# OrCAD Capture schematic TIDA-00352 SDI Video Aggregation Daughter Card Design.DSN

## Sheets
1 S01 COVER PAGE
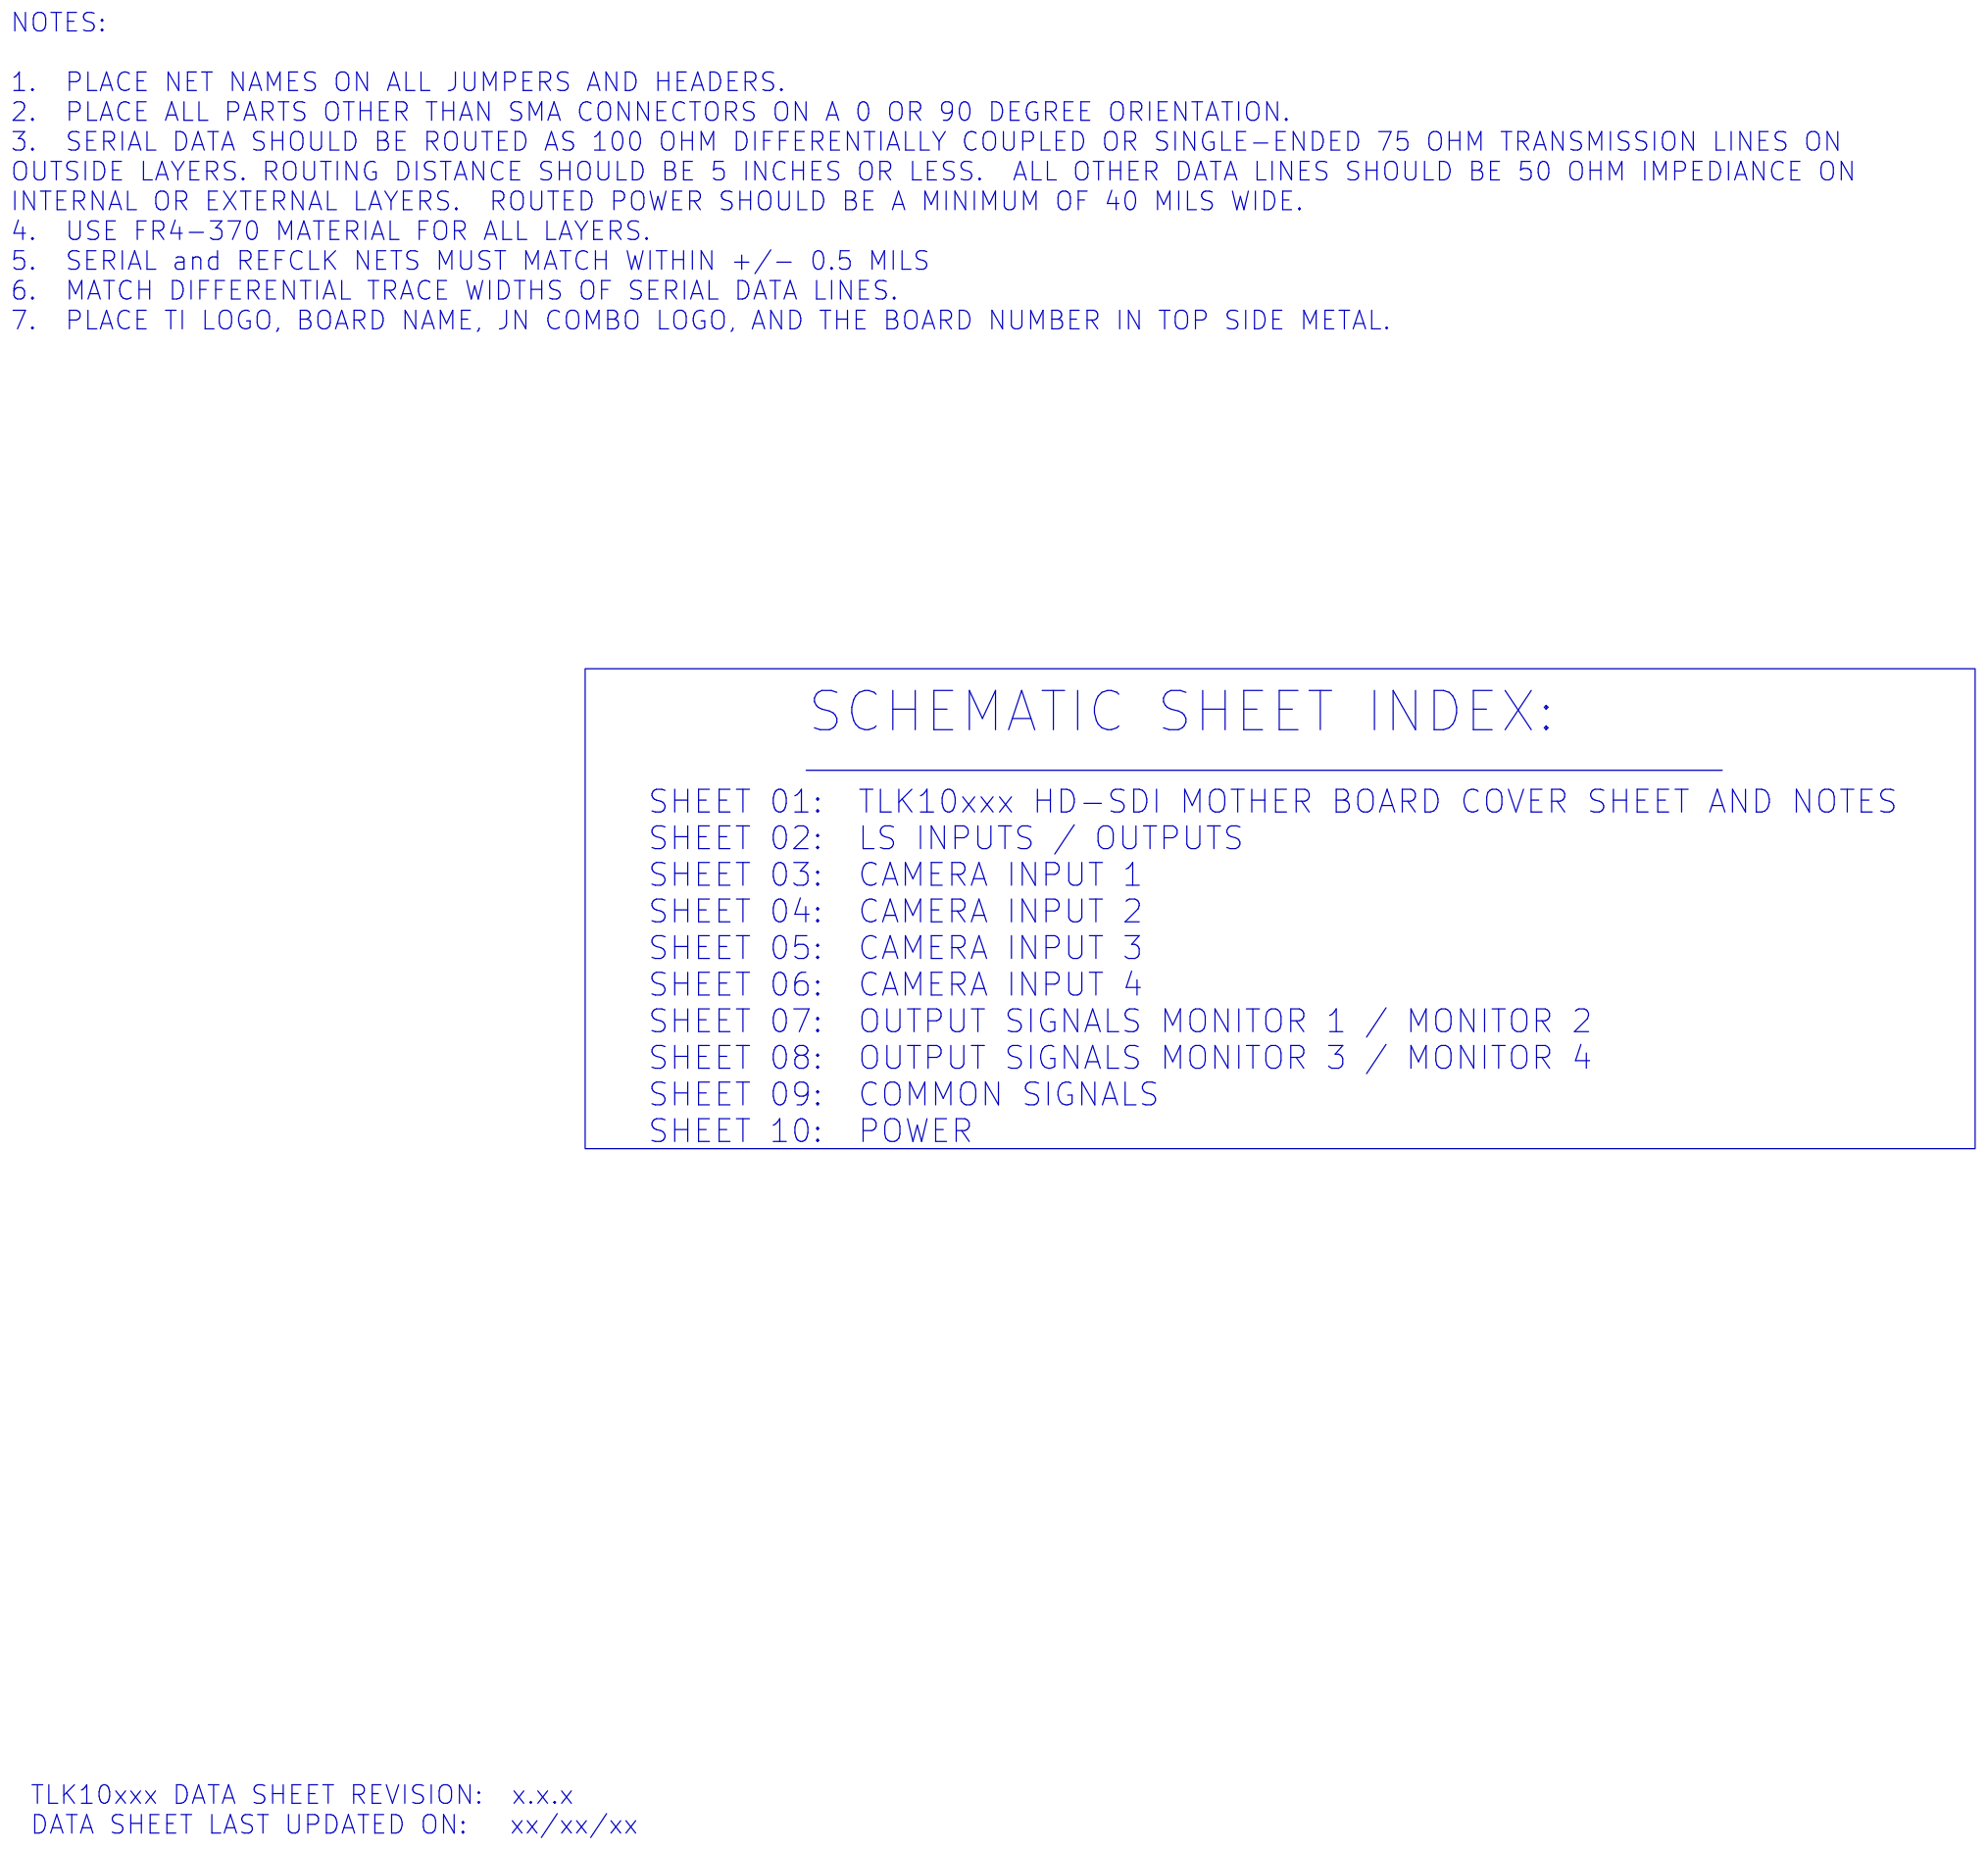
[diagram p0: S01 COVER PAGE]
2 S02 LS INPUTS_OUTPUTS: size B
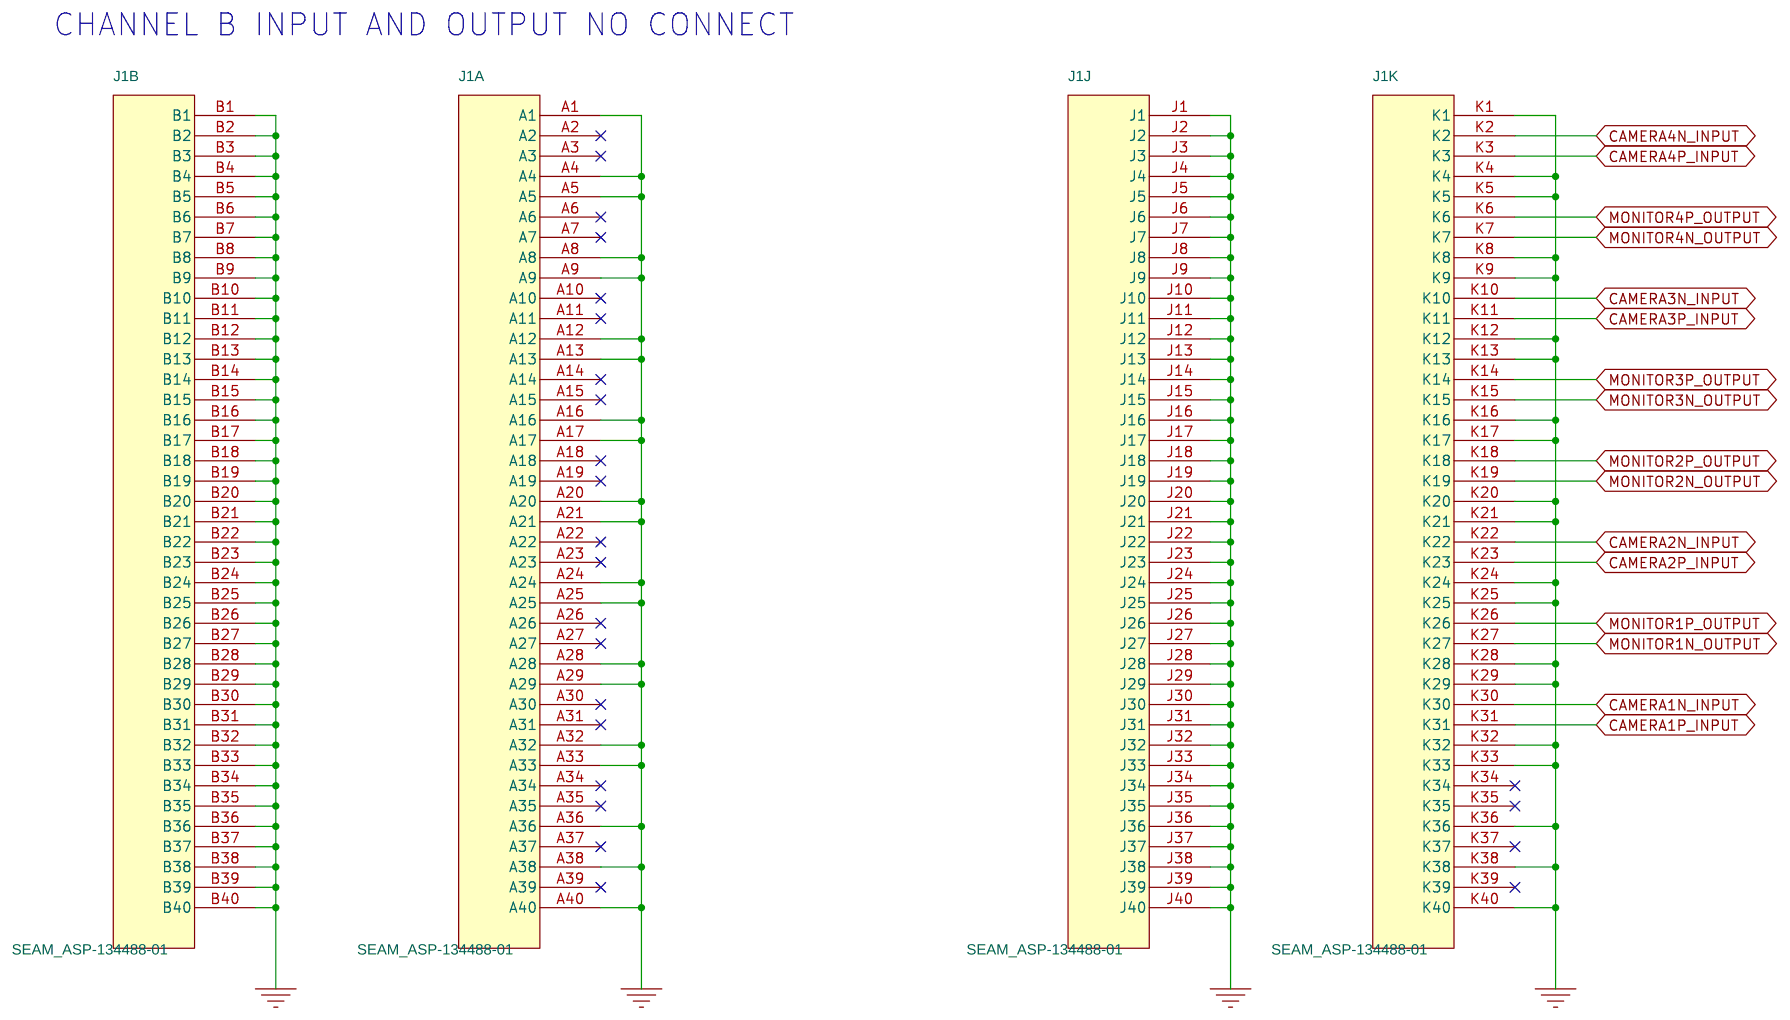
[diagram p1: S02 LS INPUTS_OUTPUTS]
3 S03 CAMERA INPUT 1: size B
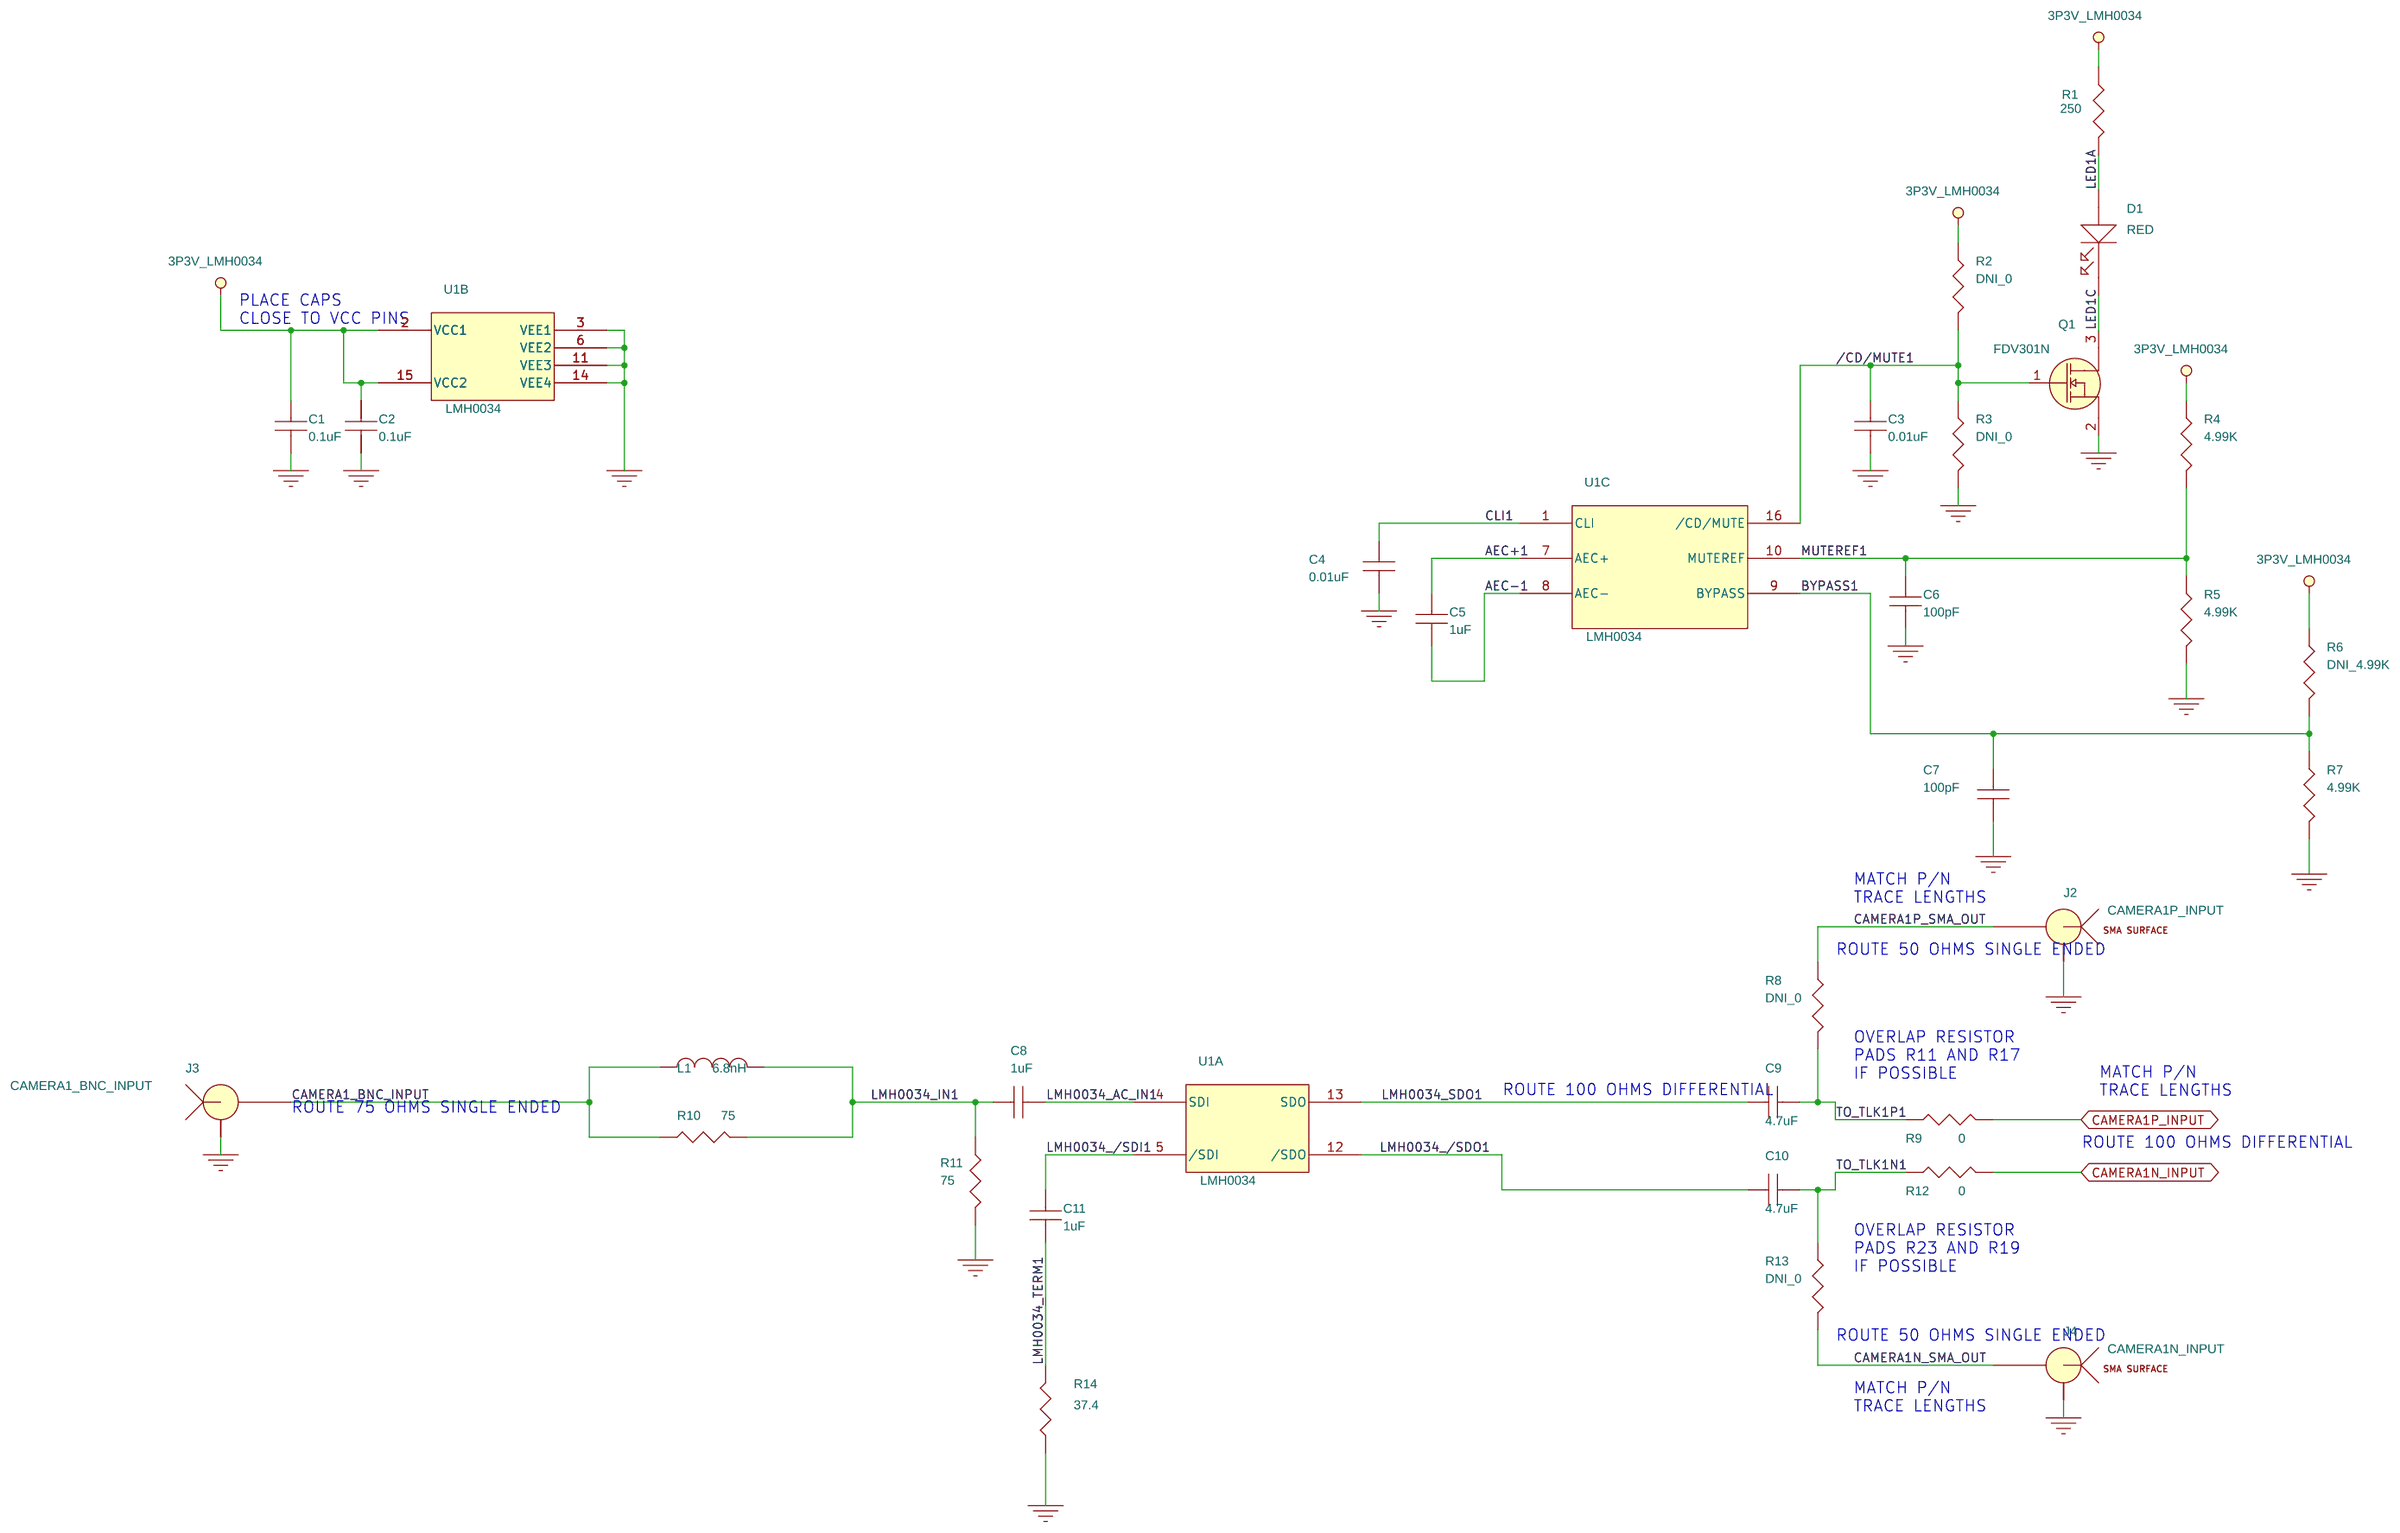
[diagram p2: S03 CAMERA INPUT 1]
4 S04 CAMERA INPUT 2: size B
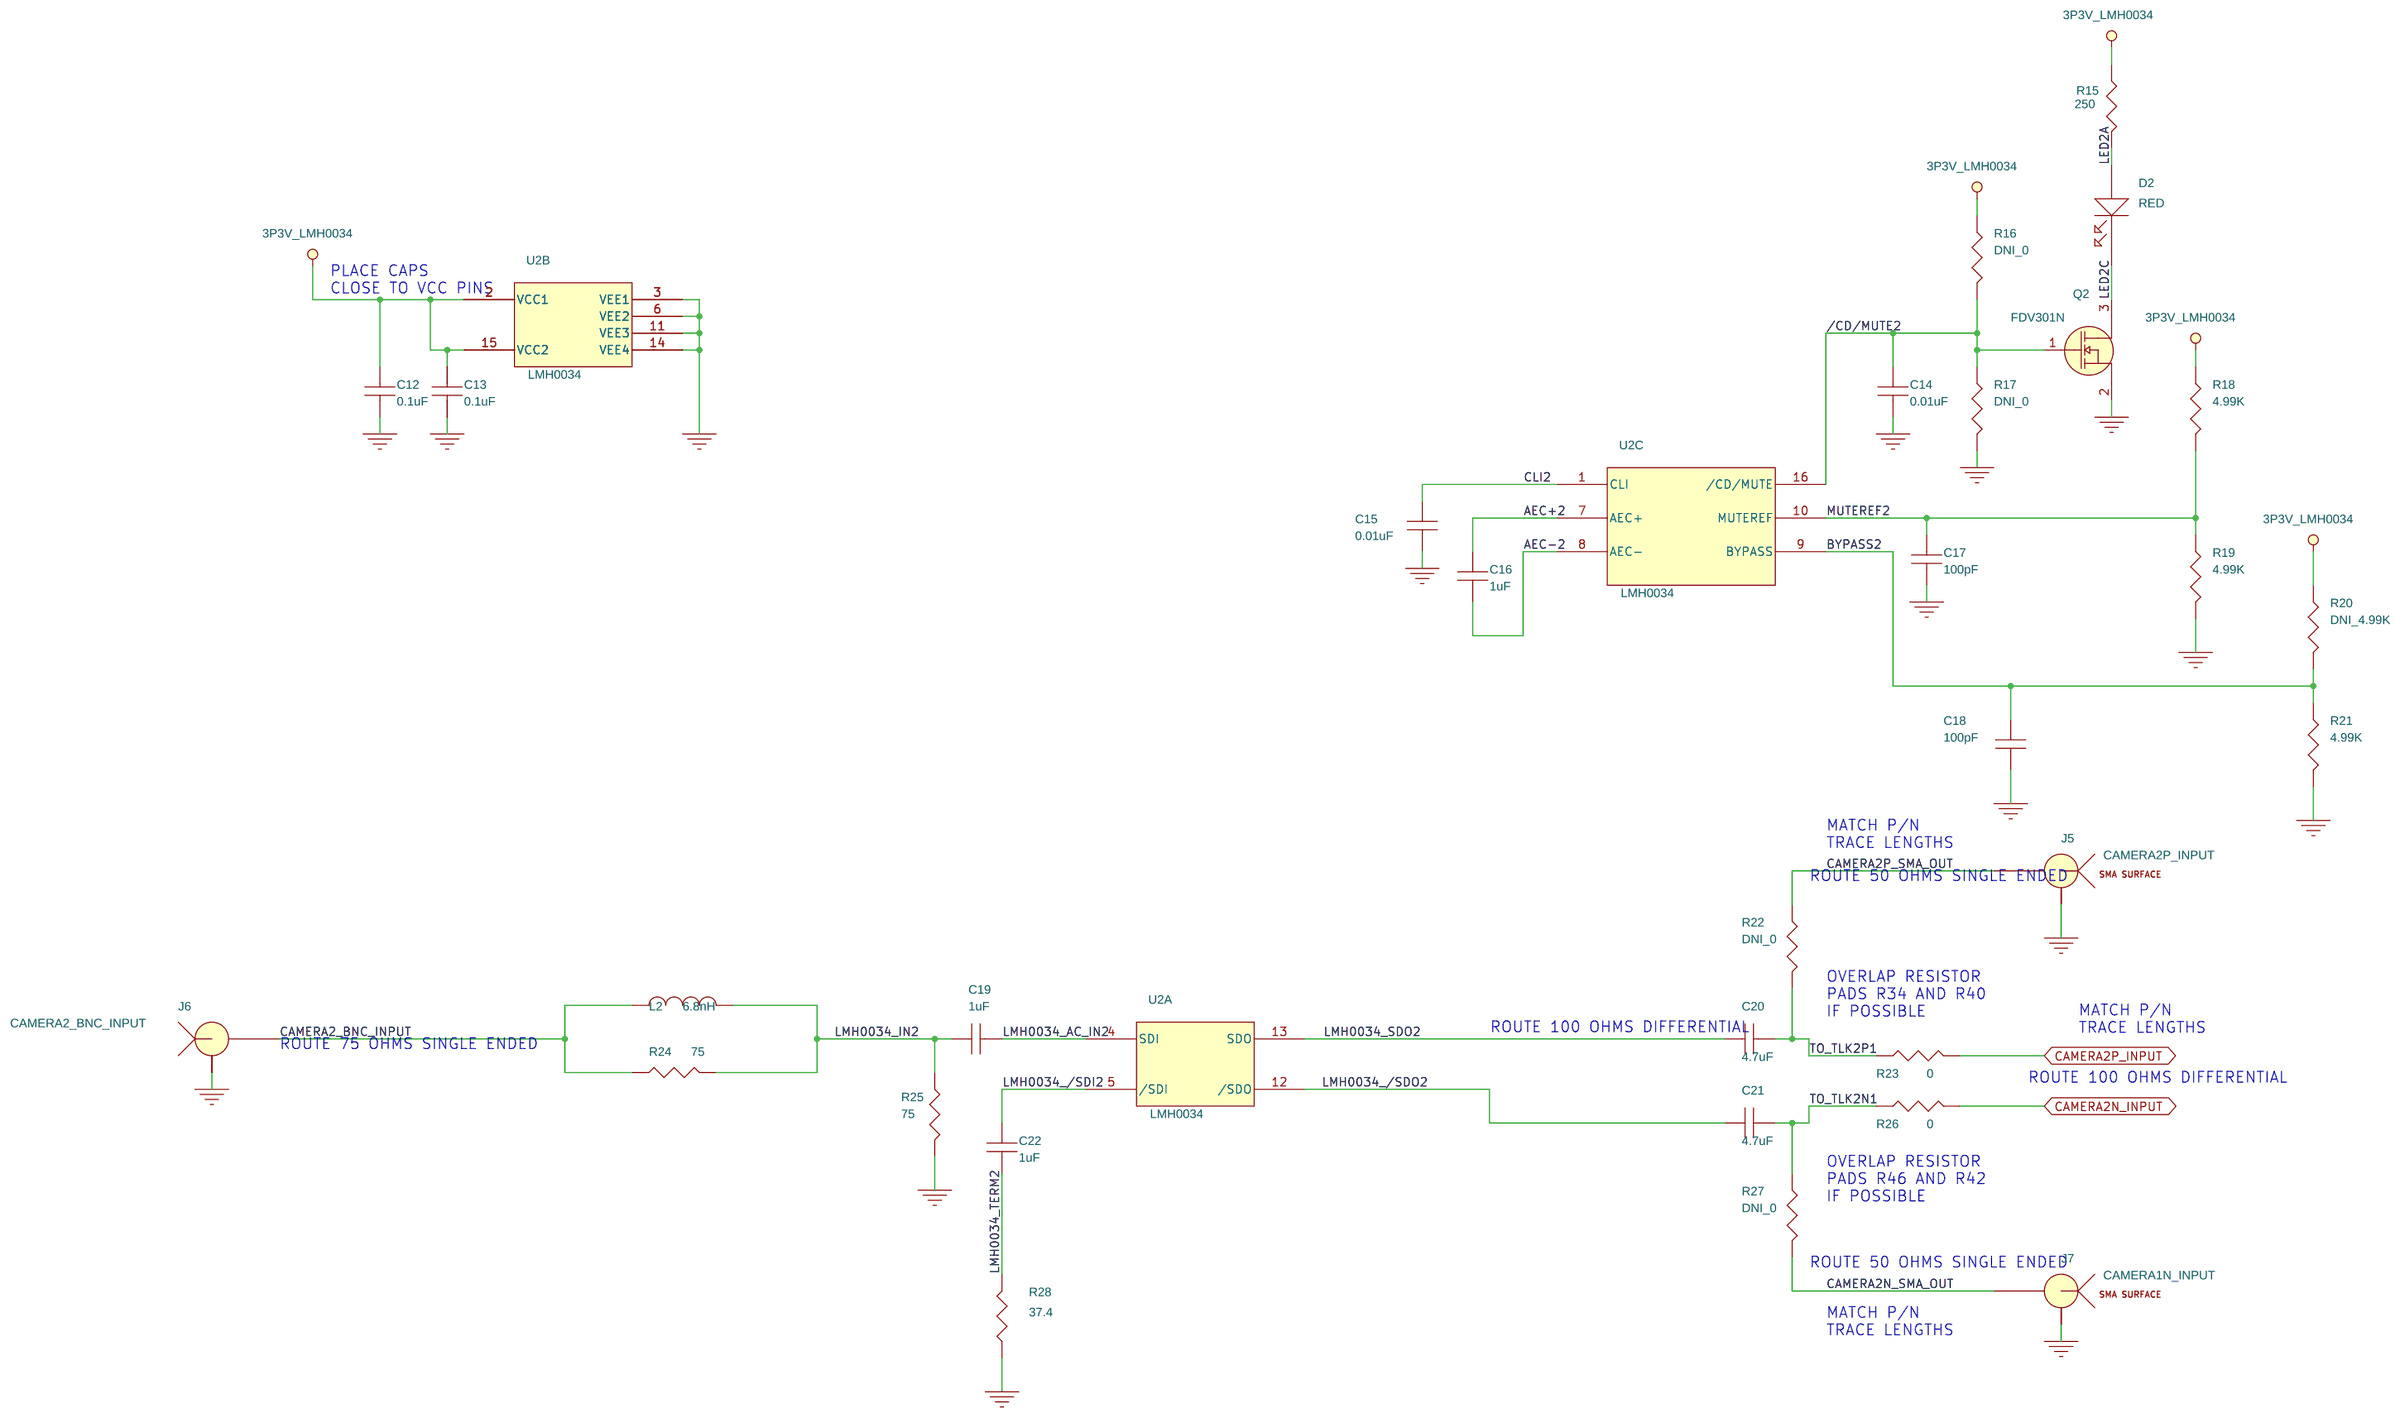
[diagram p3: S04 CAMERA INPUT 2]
5 S05 CAMERA INPUT 3: size B
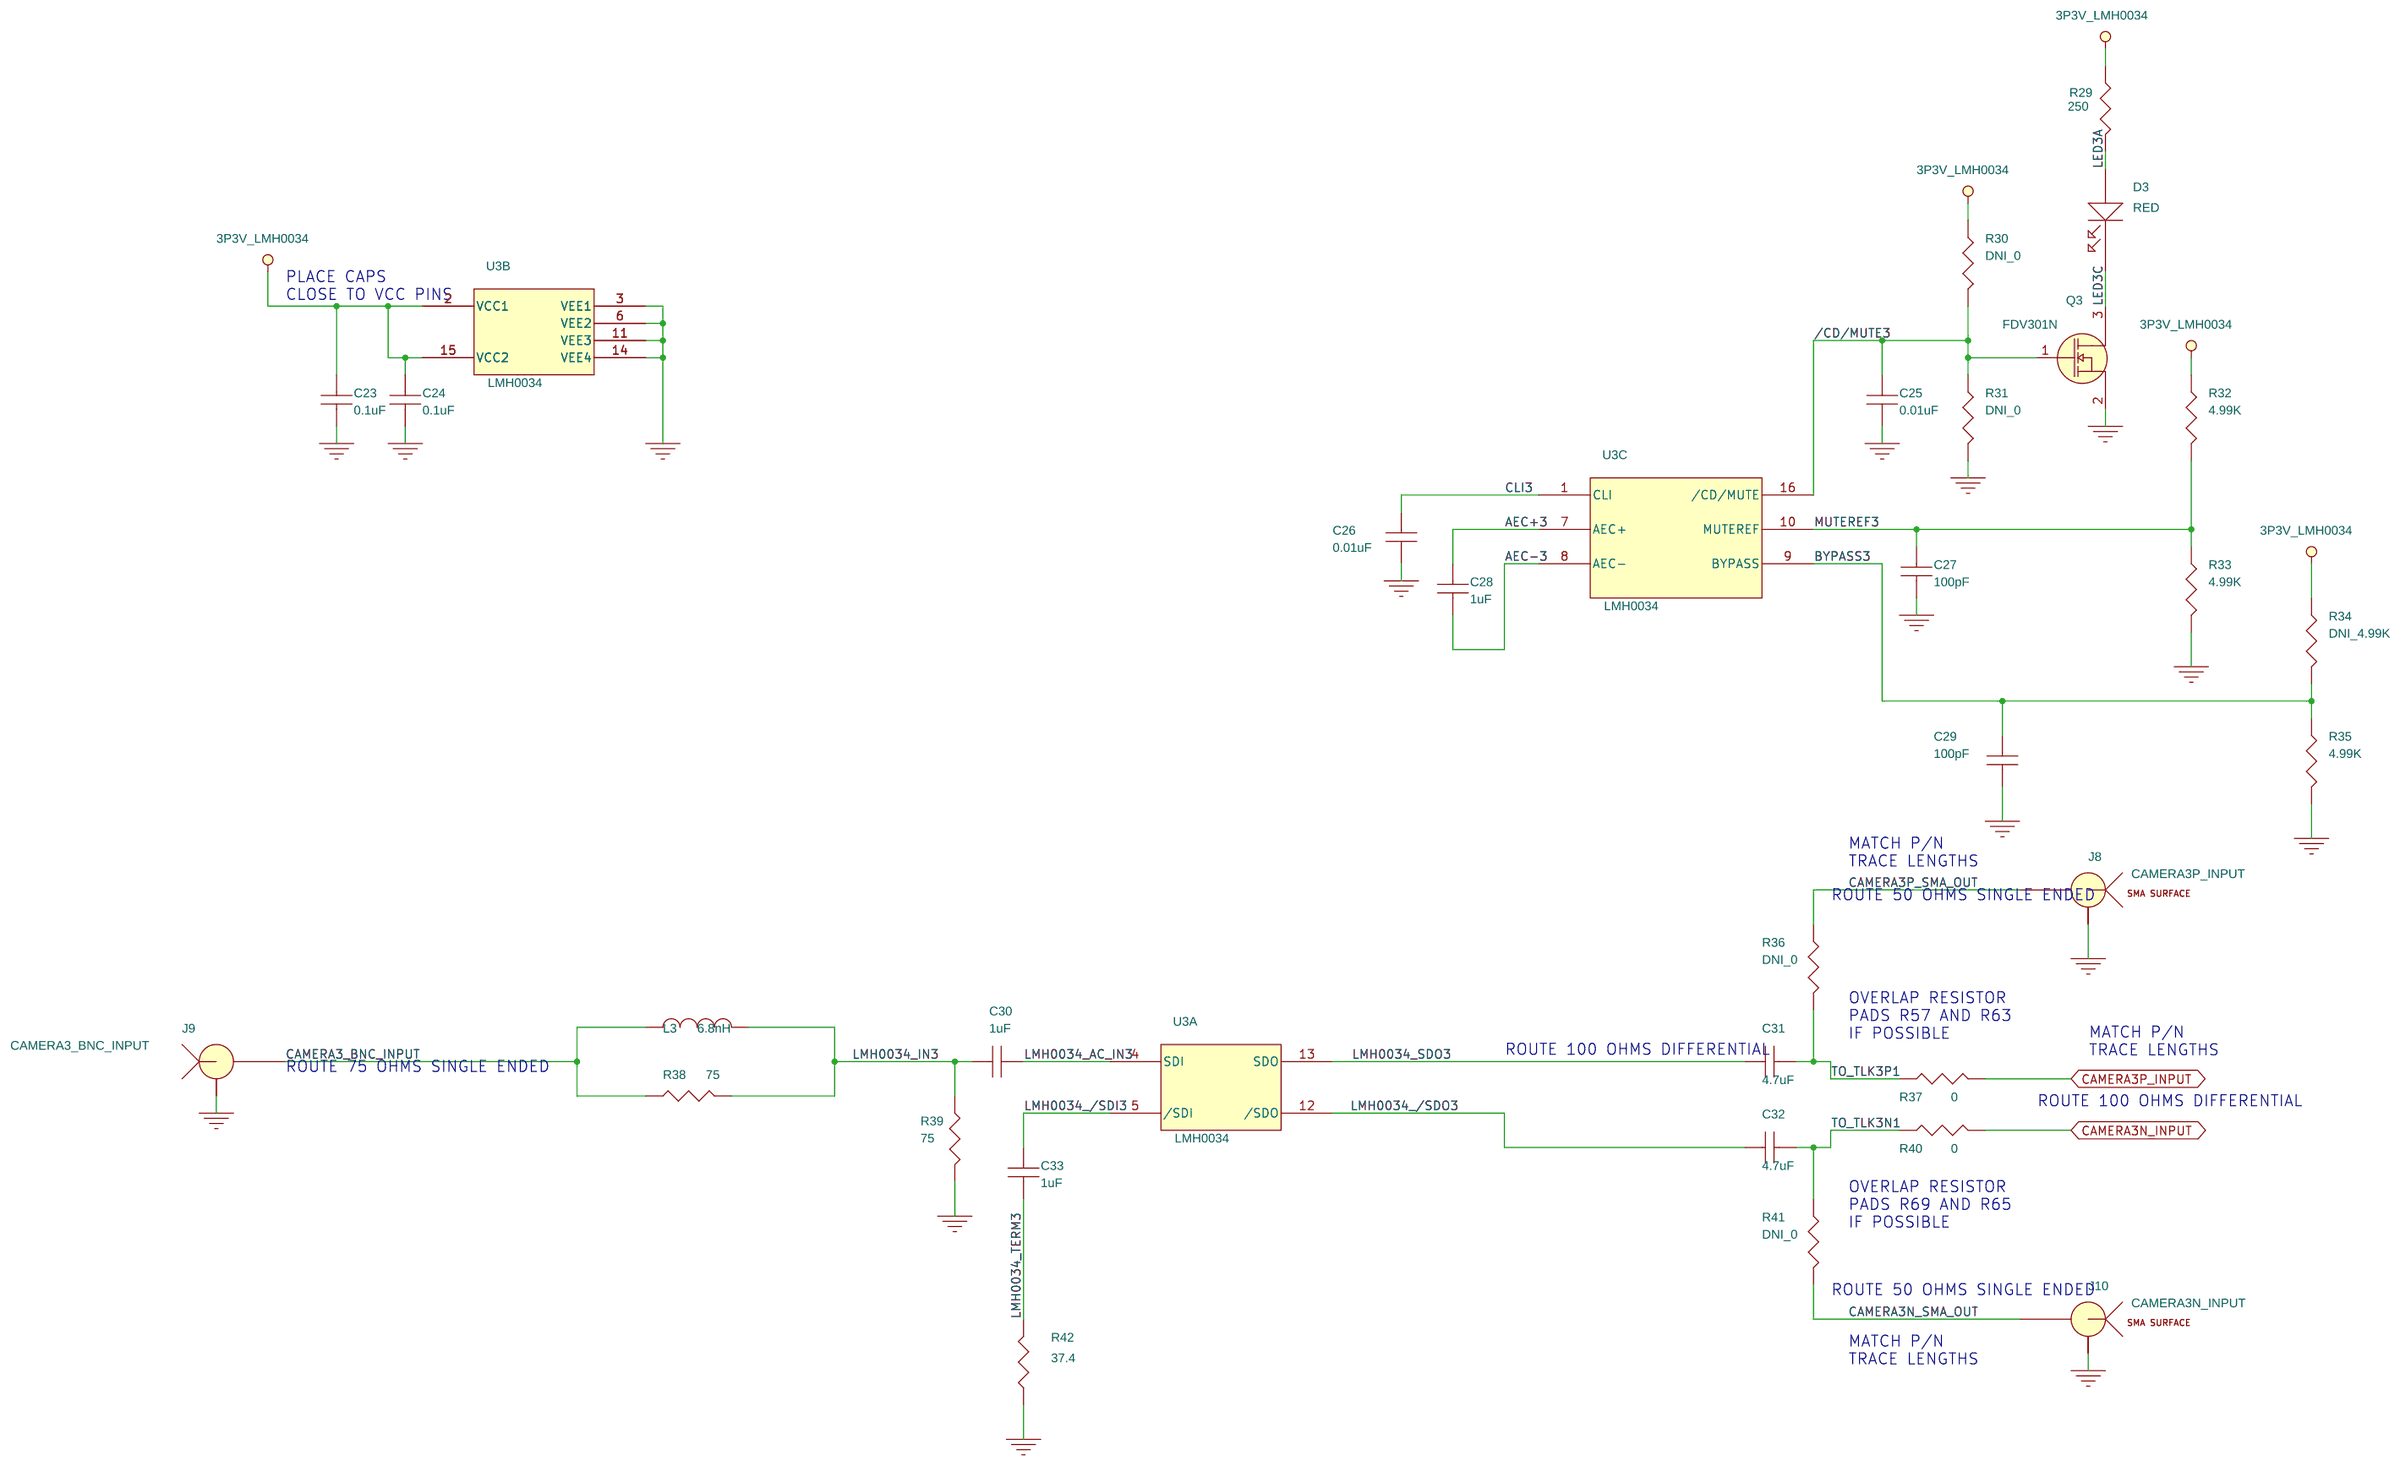
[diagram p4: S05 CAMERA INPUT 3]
6 S06 CAMERA INPUT 4: size B
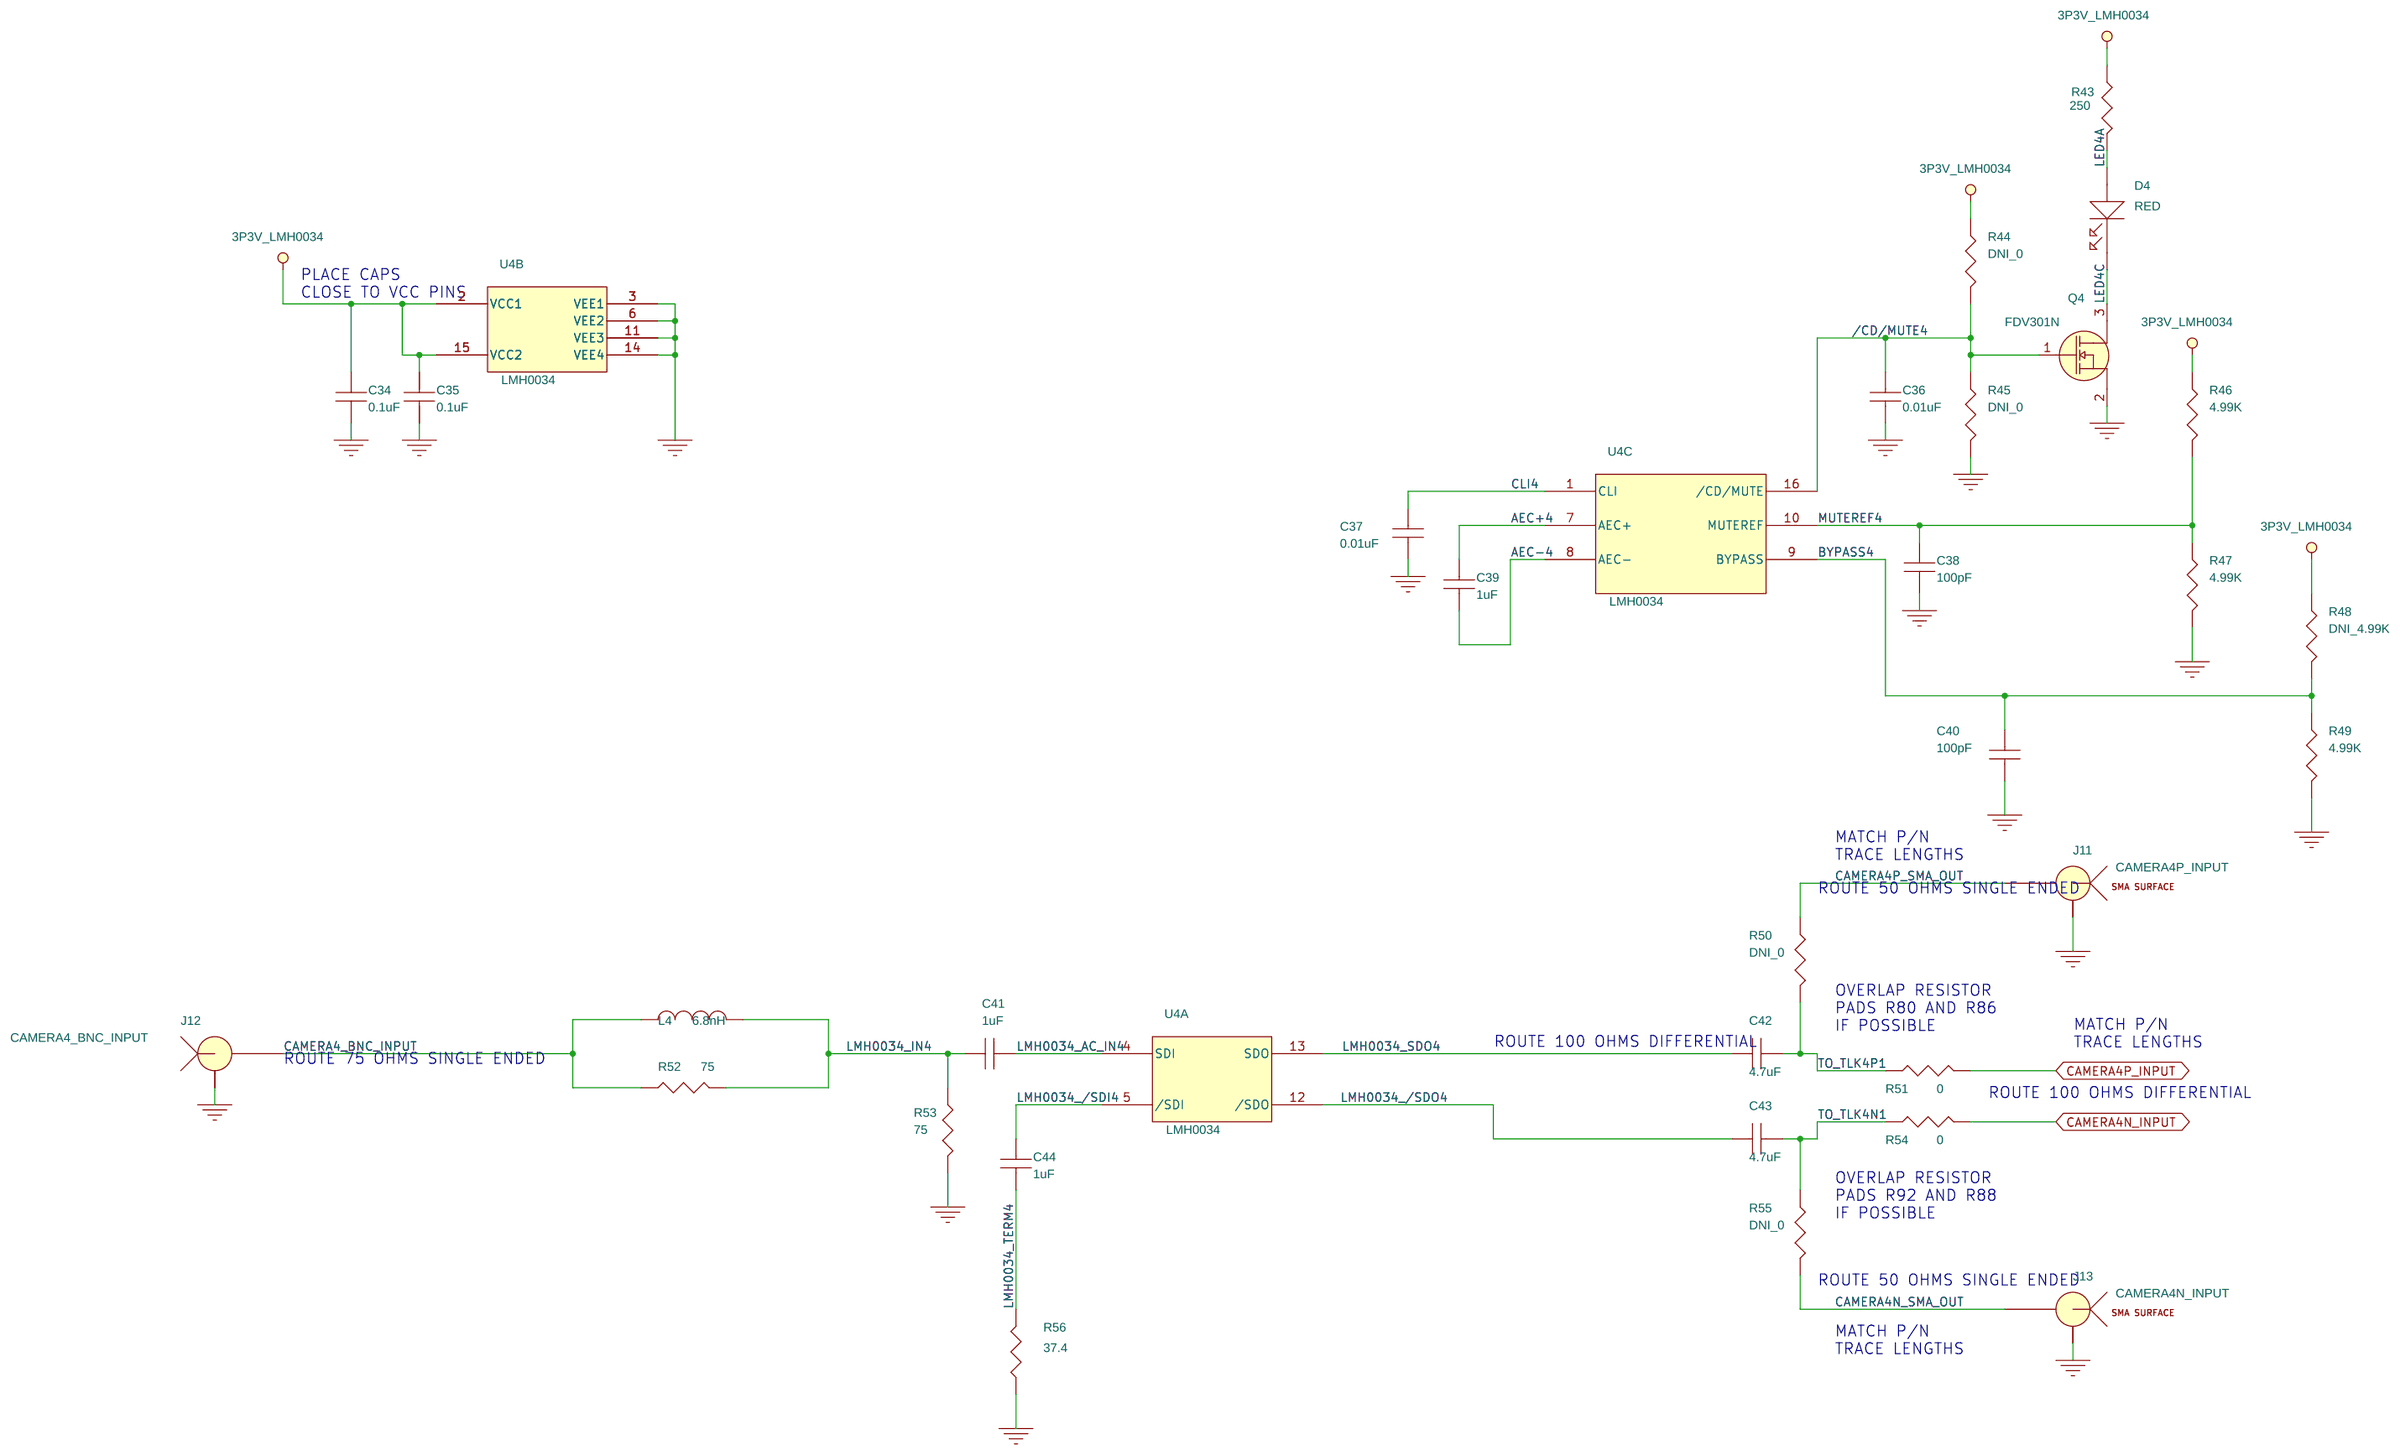
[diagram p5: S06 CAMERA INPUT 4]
7 S07 OUTPUT SIGNALS 1: size B
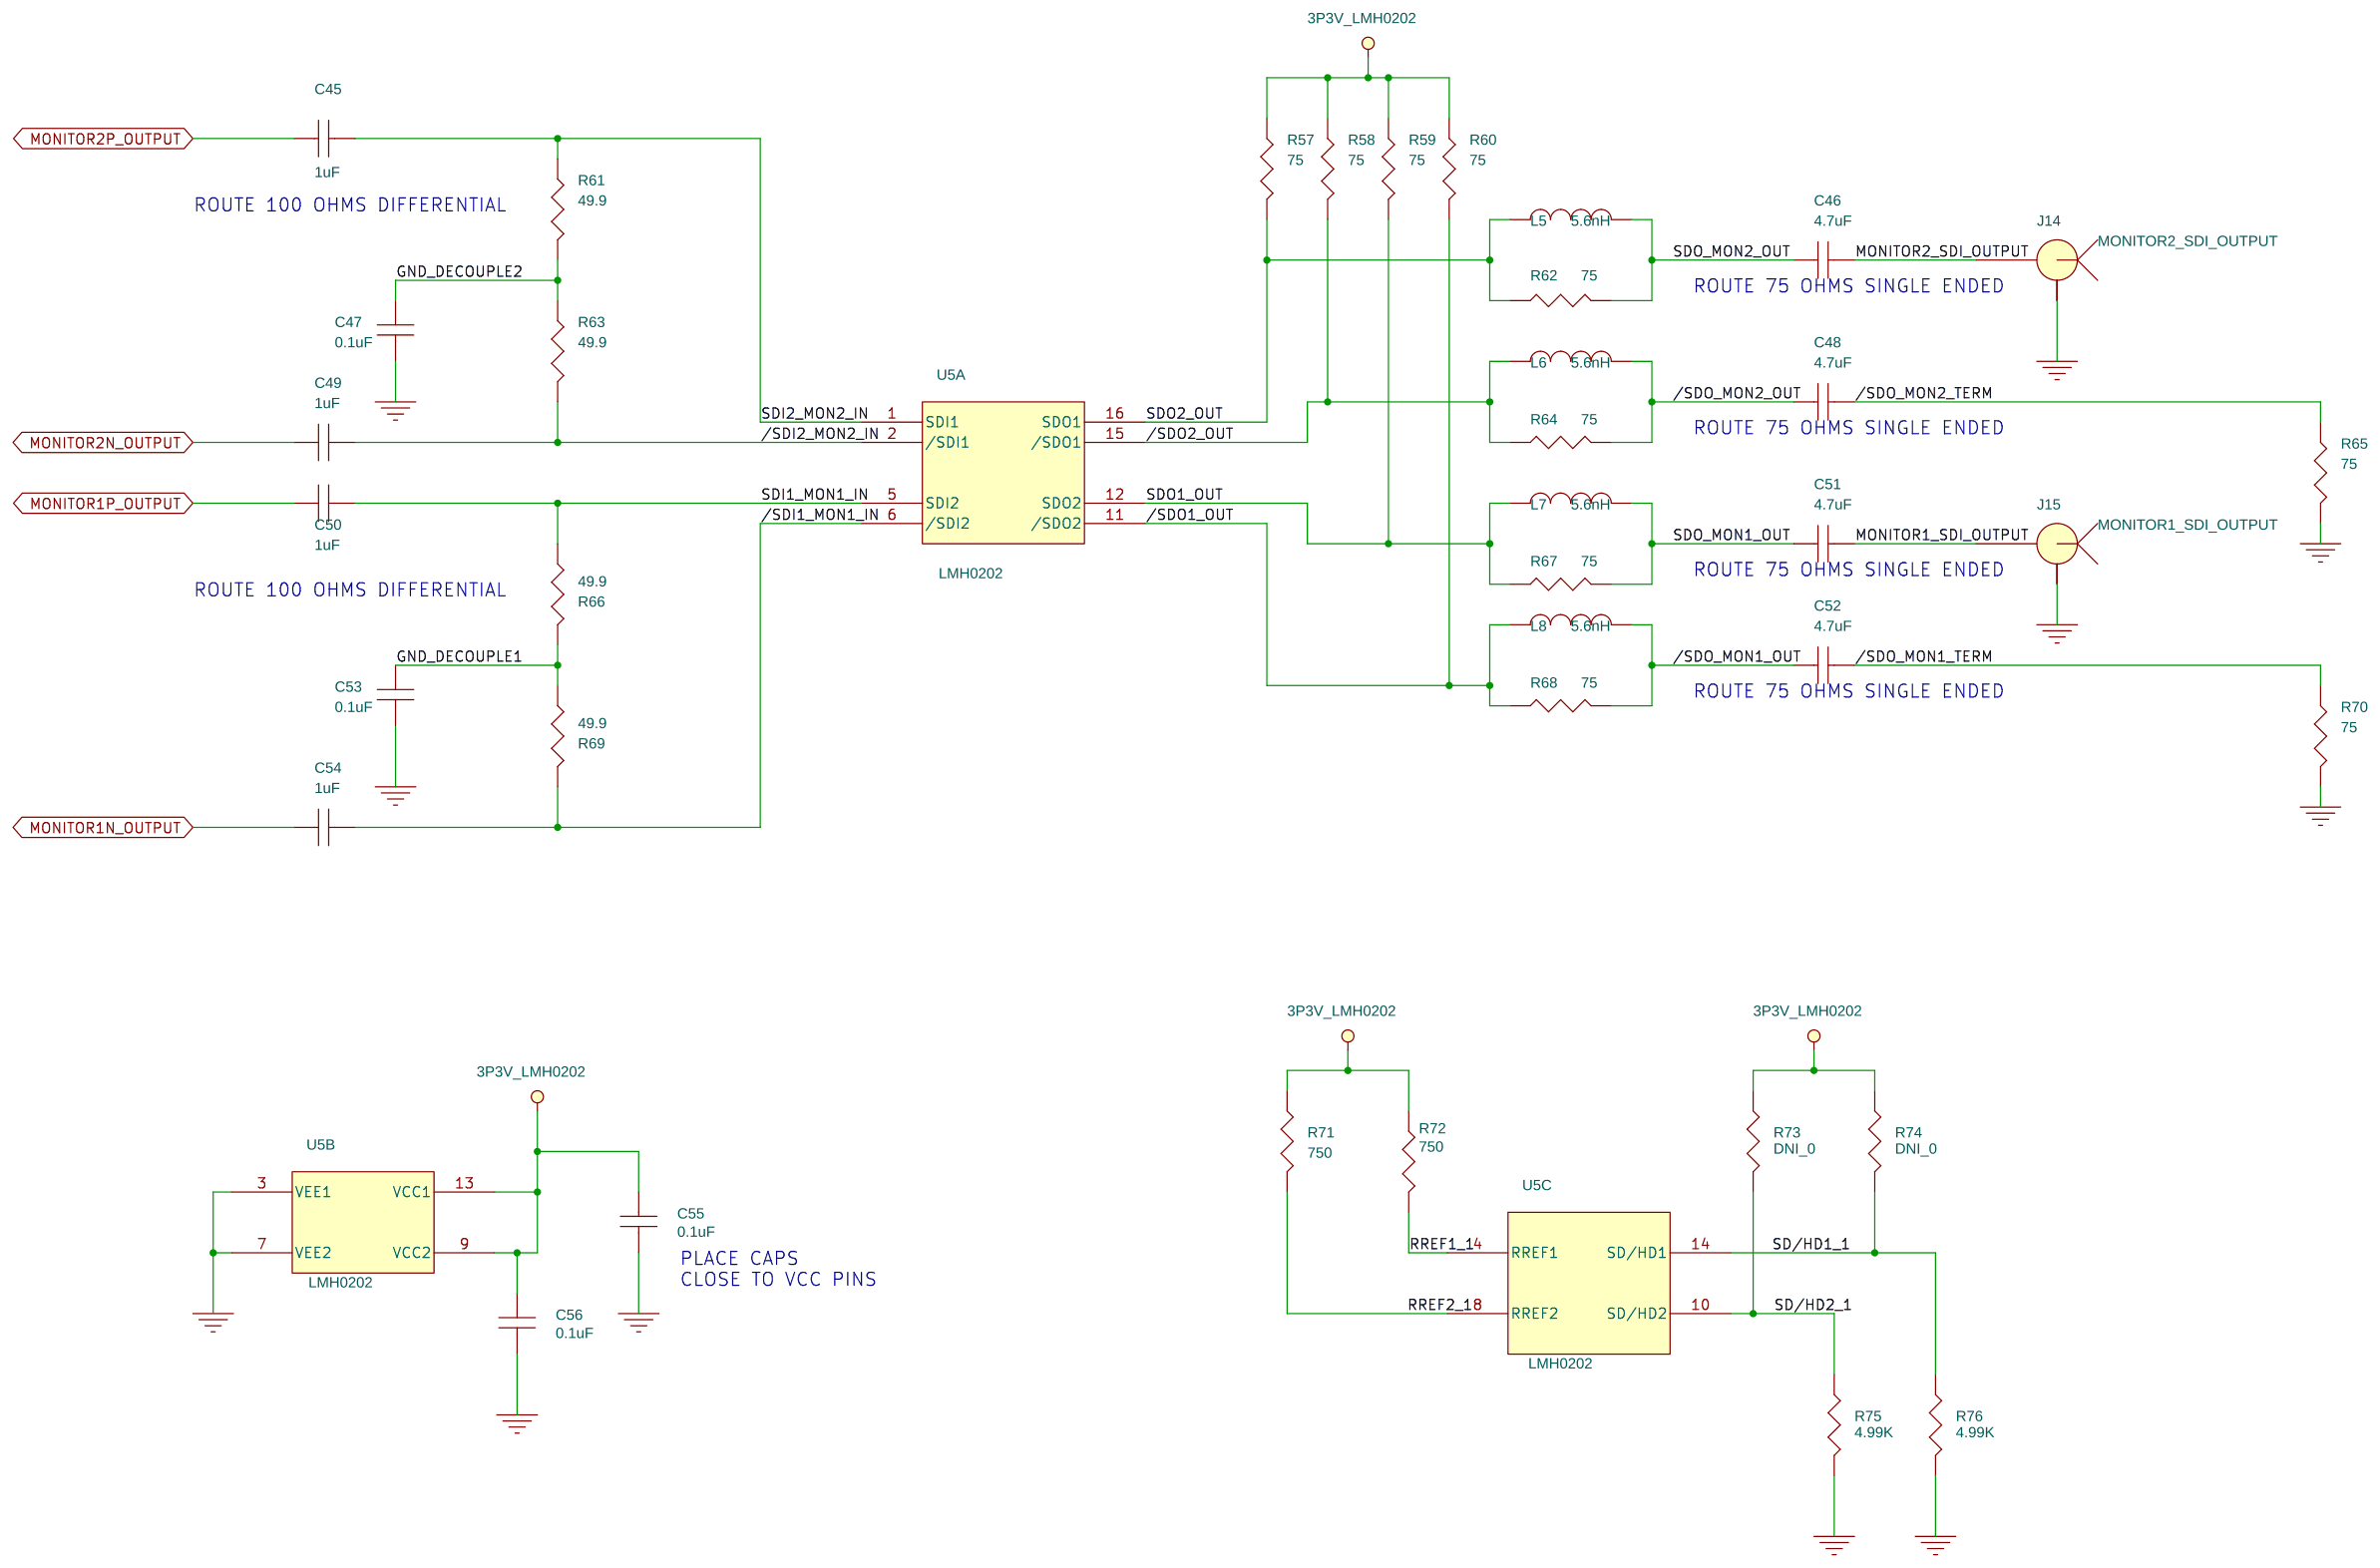
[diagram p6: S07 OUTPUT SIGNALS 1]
8 S08 OUTPUT SIGNALS 2: size B
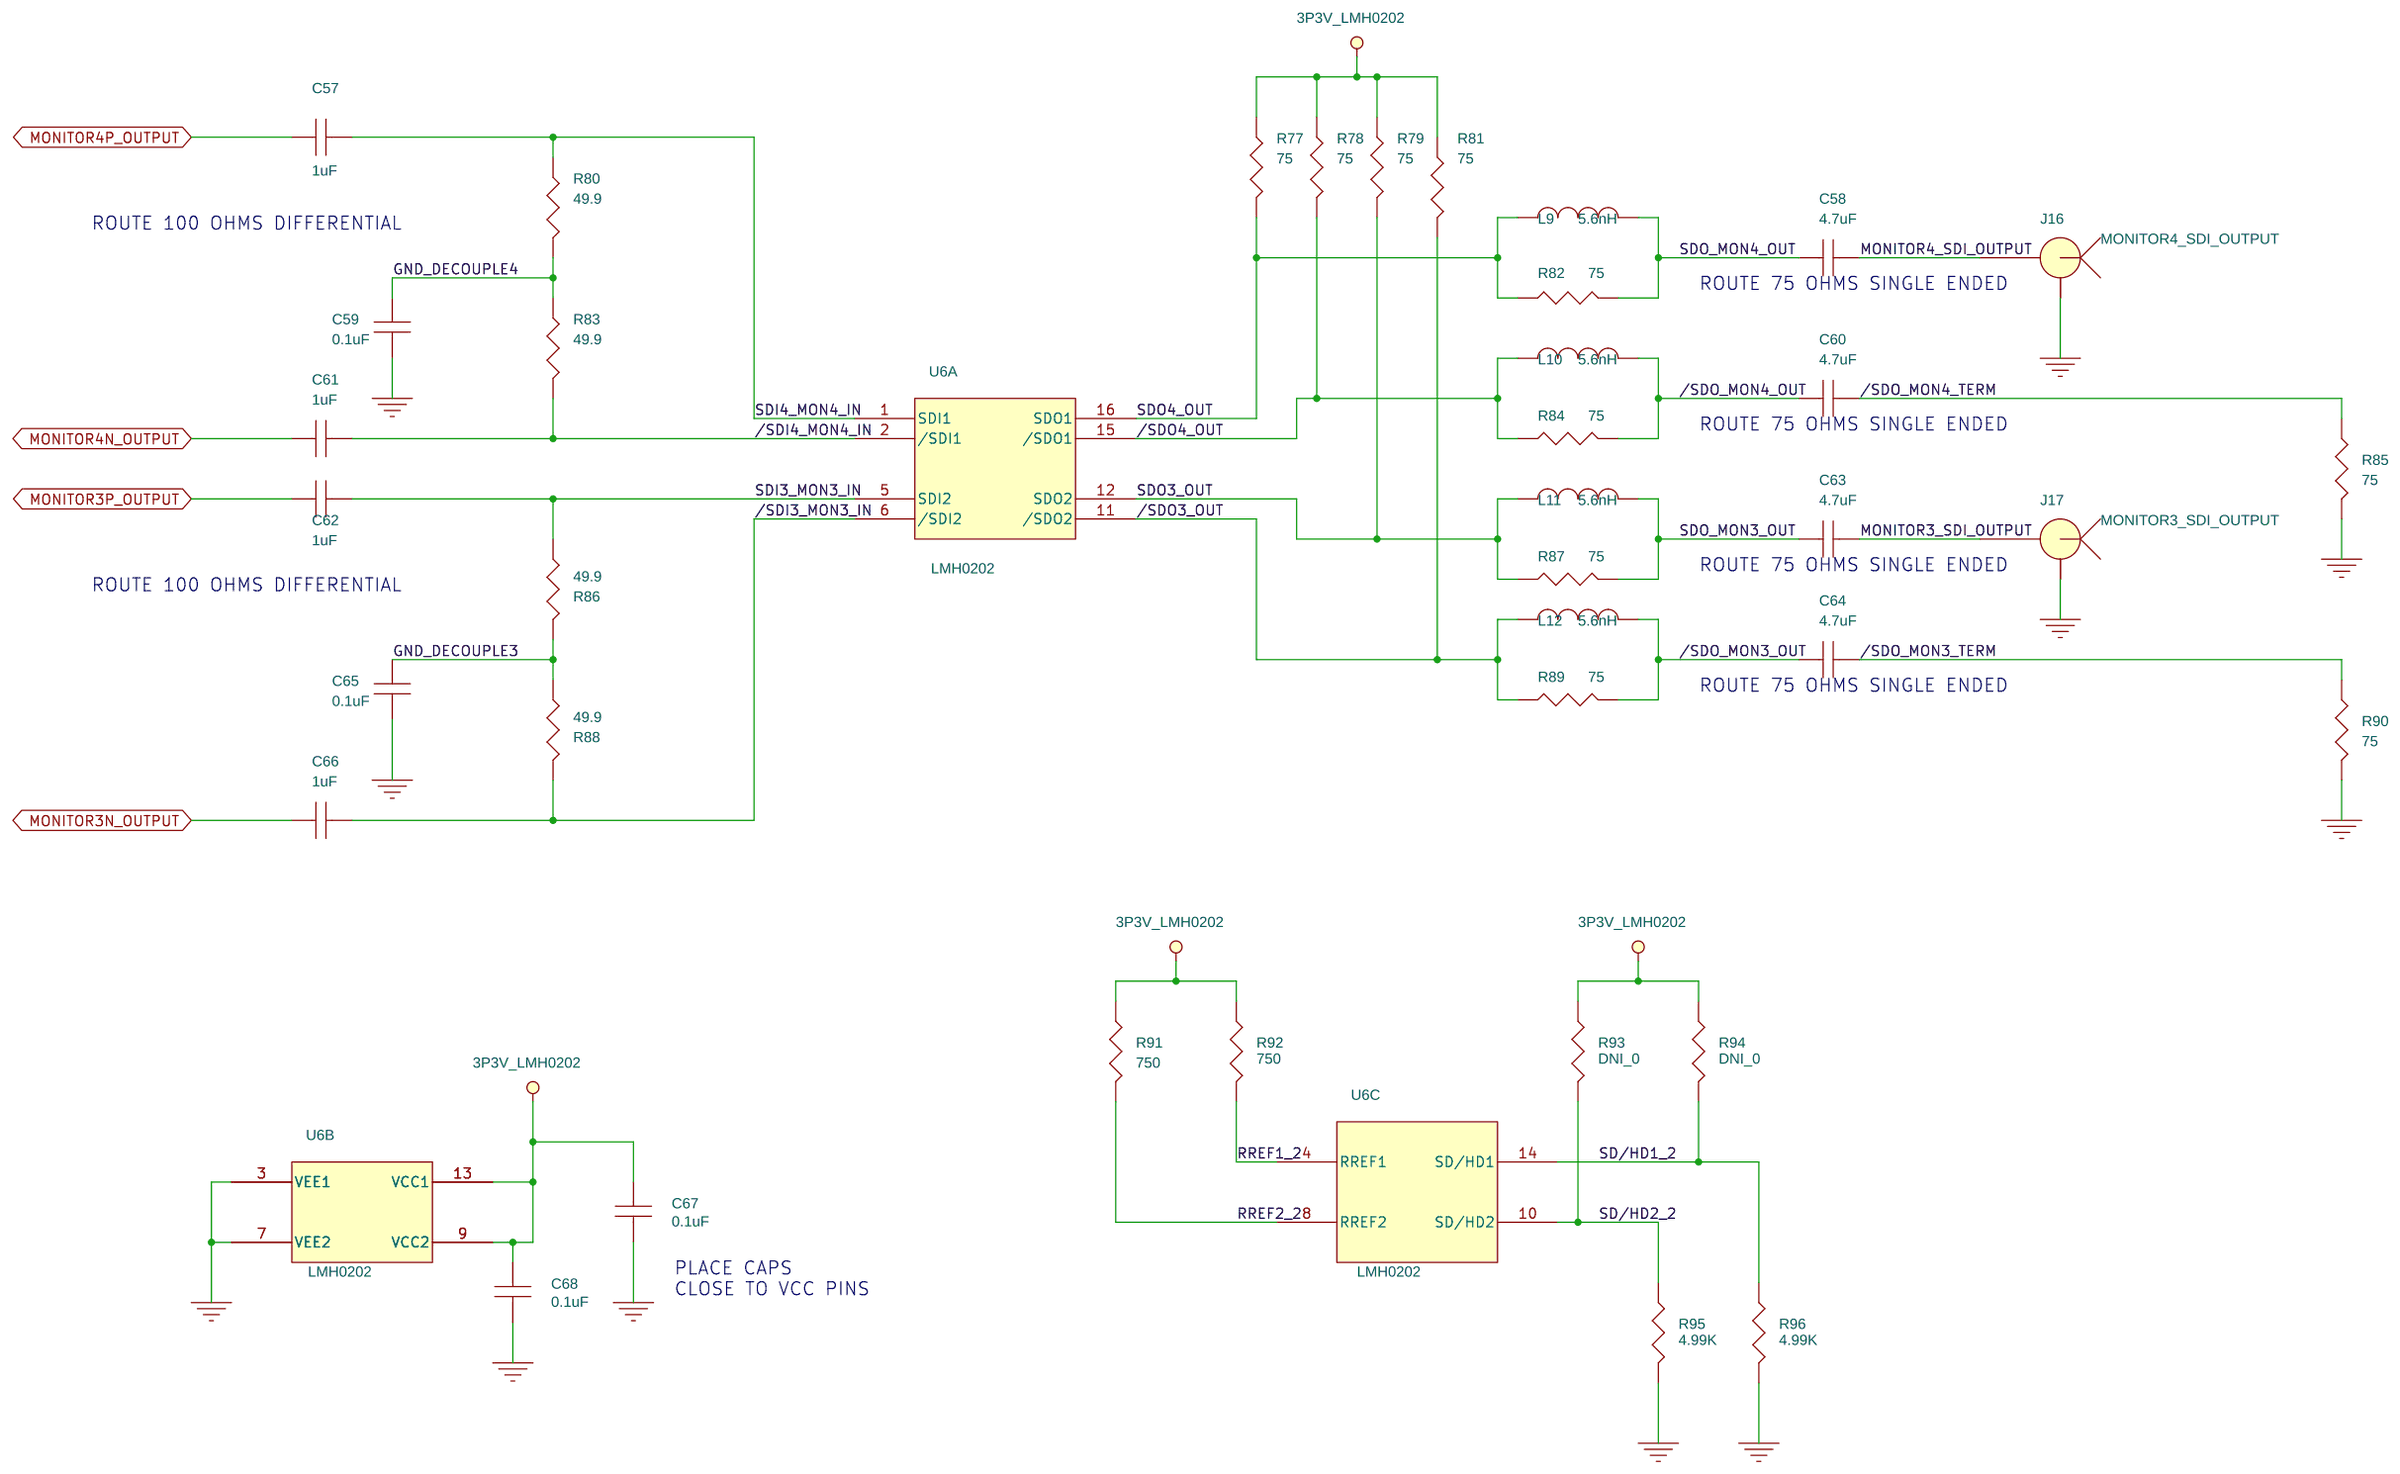
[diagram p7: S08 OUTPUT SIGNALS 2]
9 S09COMMON SIGNALS: size B
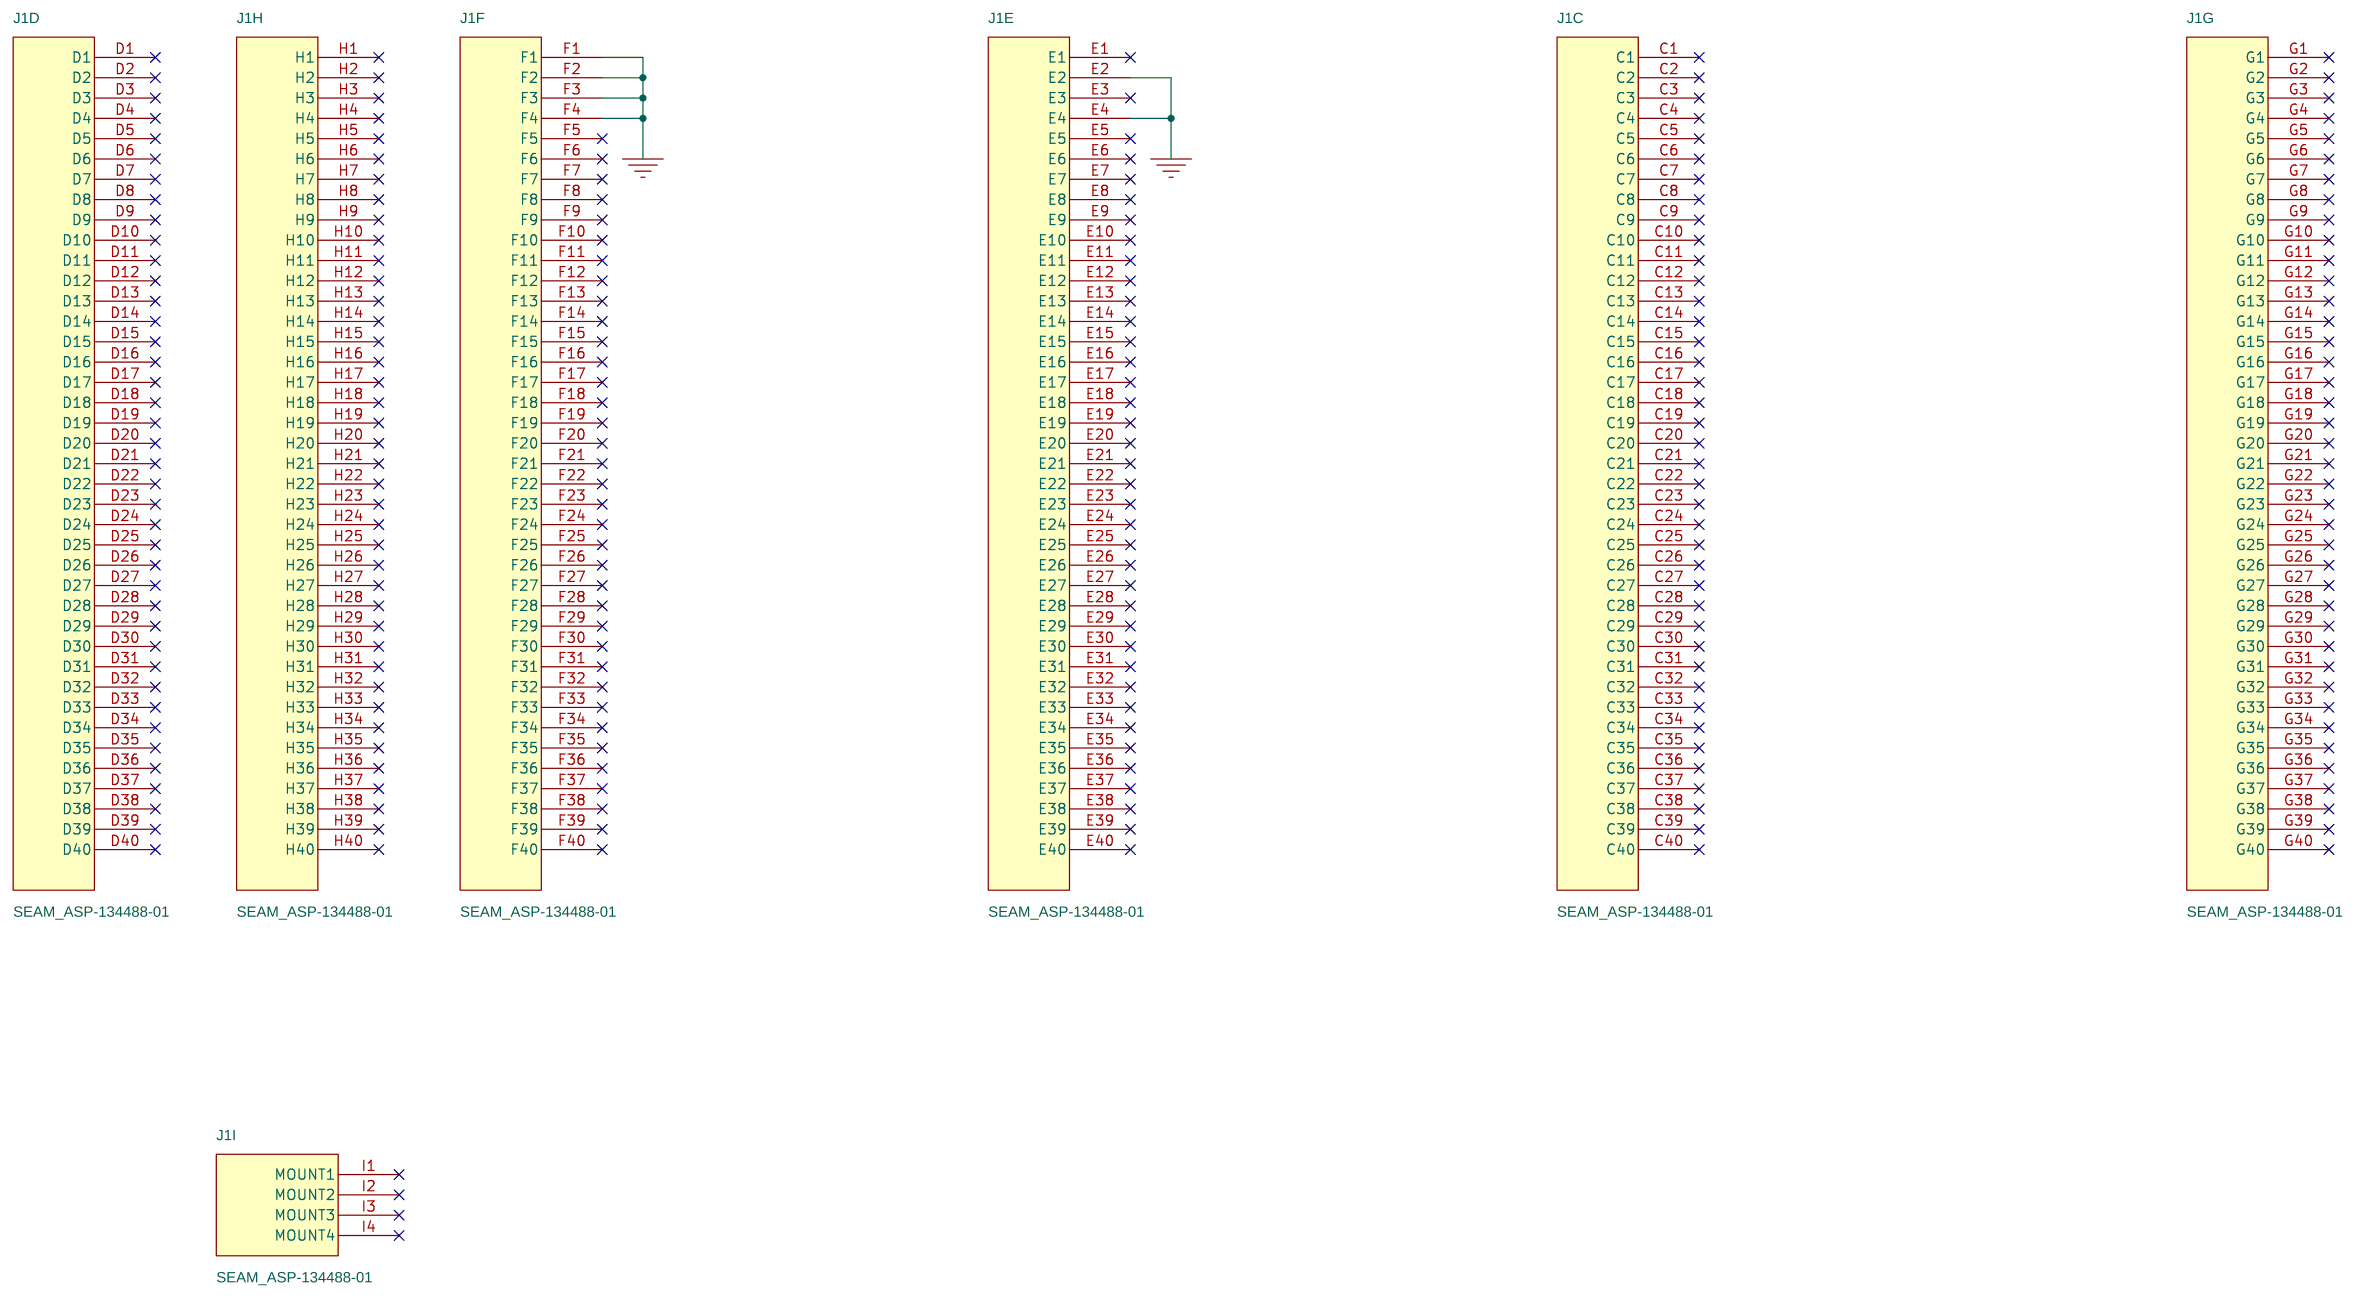
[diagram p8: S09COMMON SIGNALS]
10 S10 POWER: size B
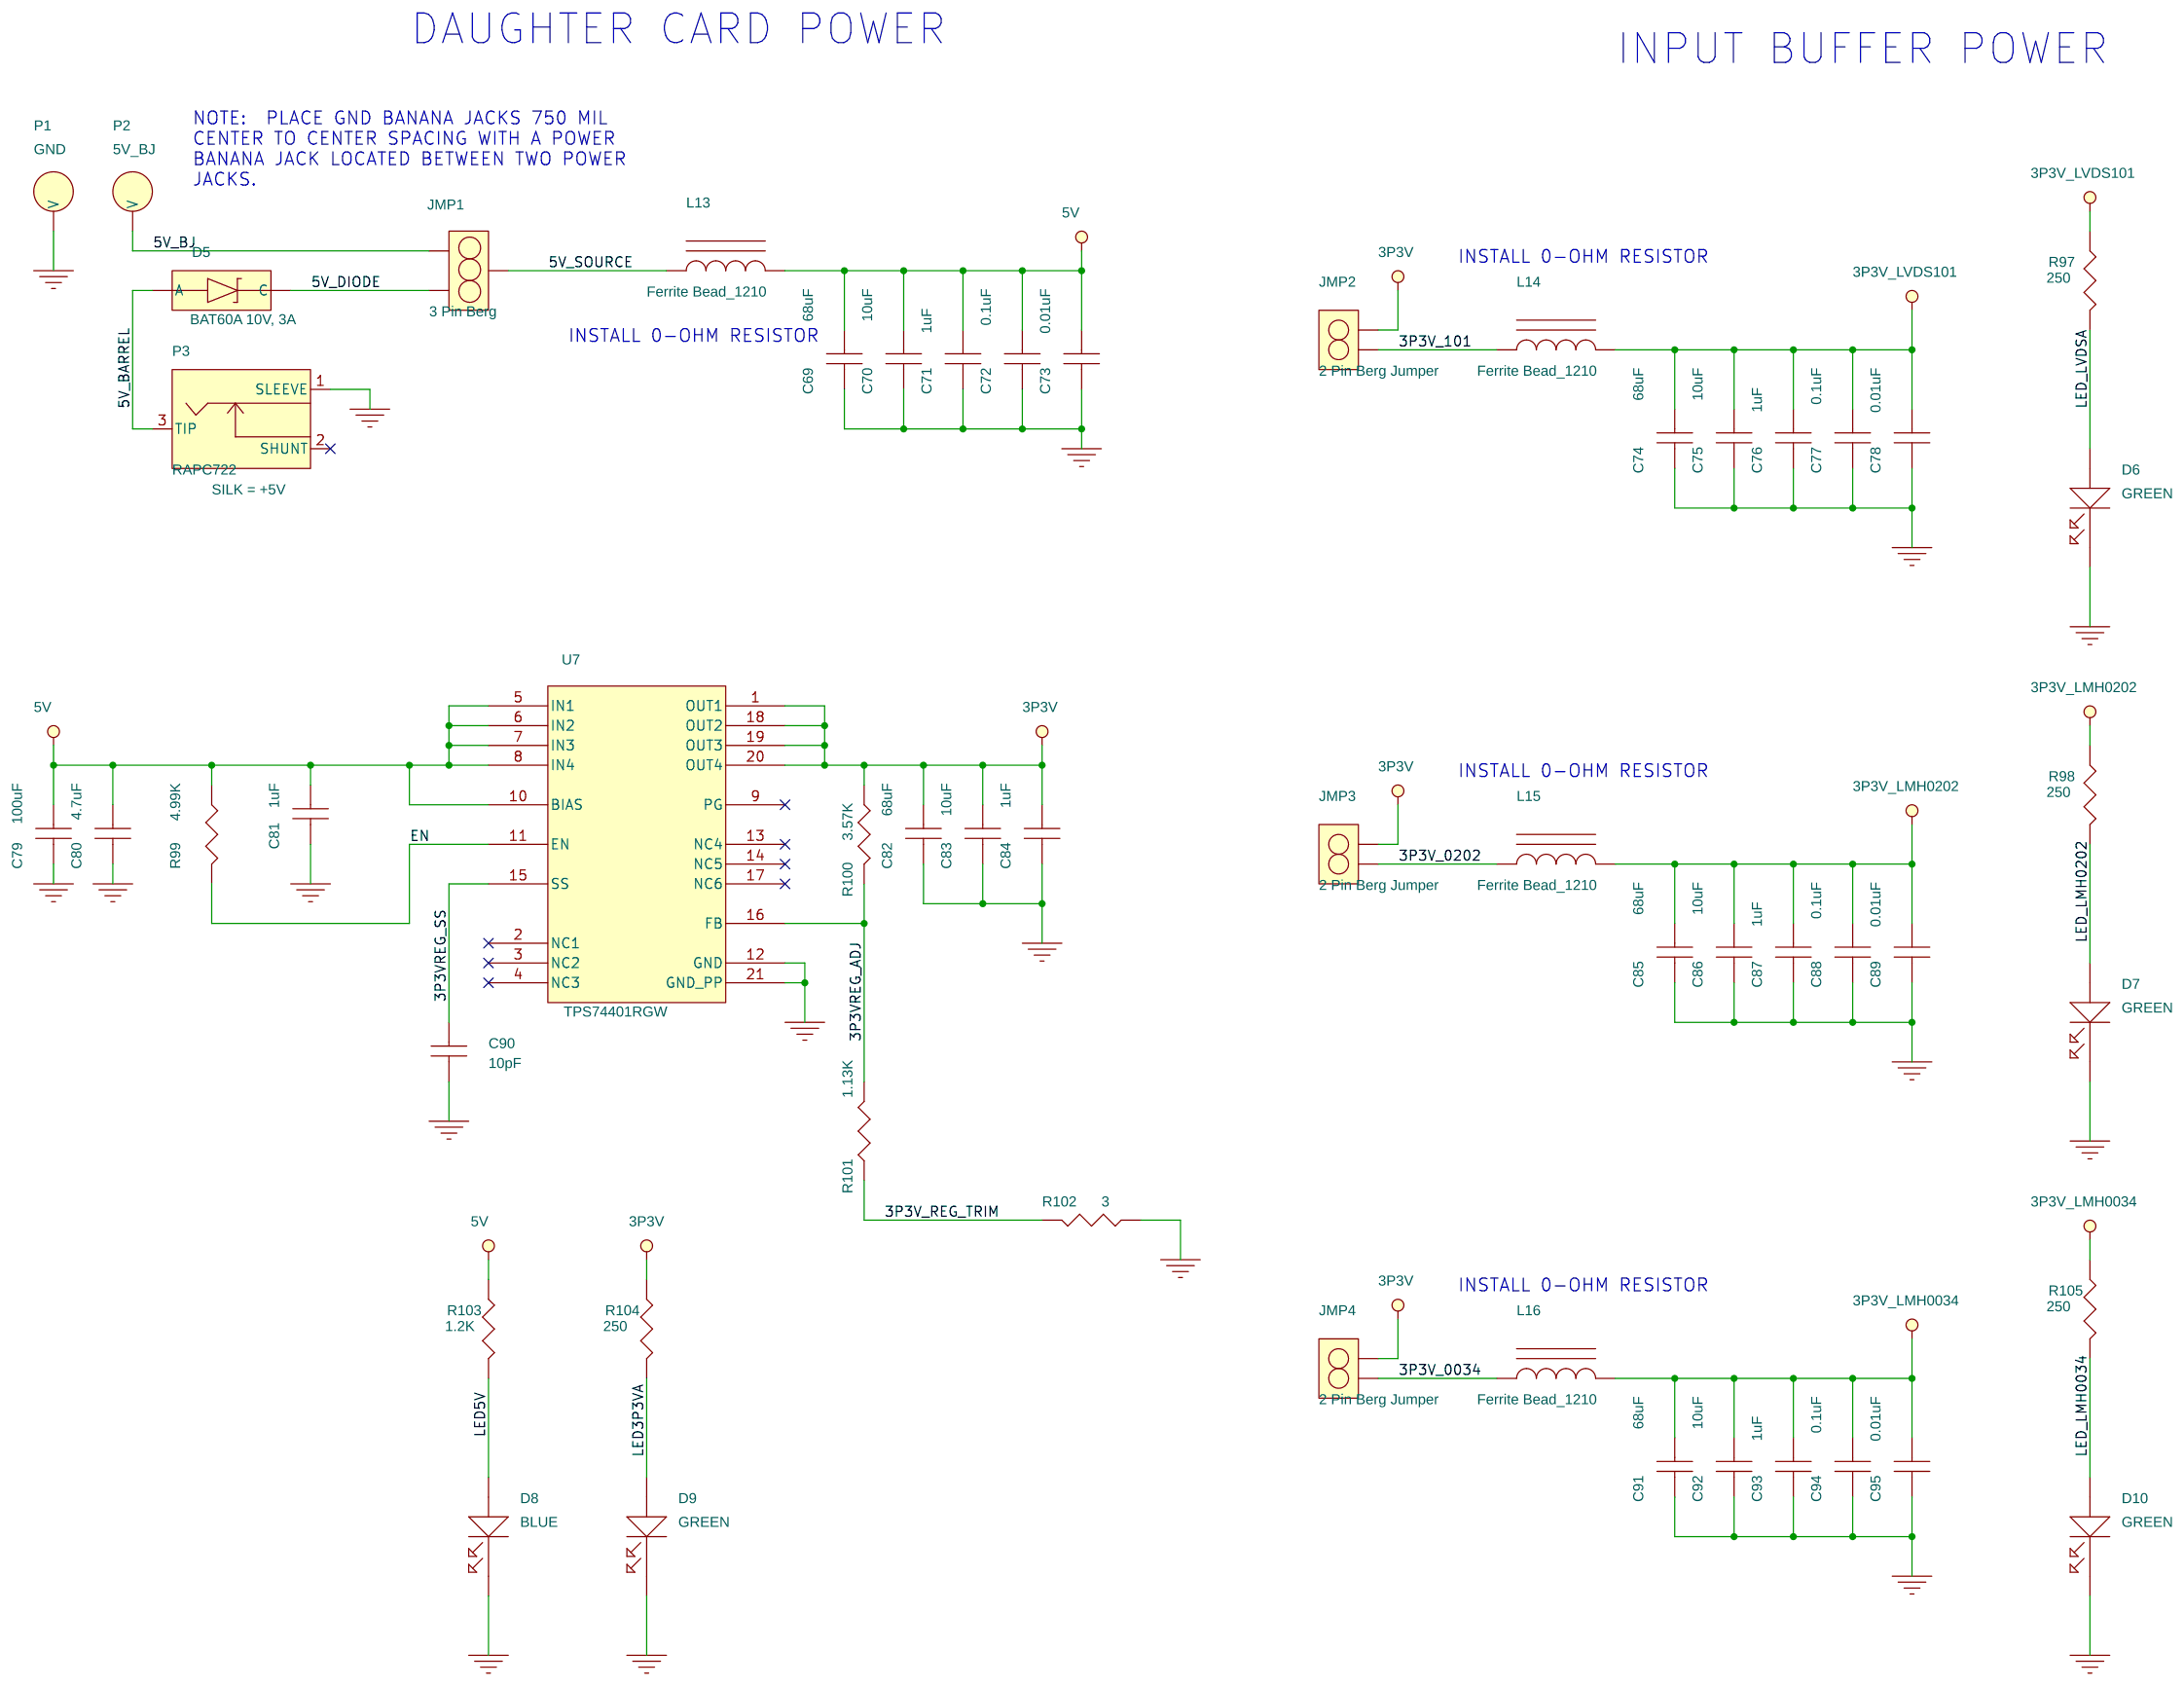
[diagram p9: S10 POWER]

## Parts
sheet S03 CAMERA INPUT 1
C1  0.1uF  [0402]
C2  0.1uF  [0402]
C3  0.01uF  [0402]
C4  0.01uF  [0402]
C5  1uF  [0402]
C6  100pF  [0402]
C7  100pF  [0402]
C8  1uF  [0603]
C9  4.7uF  [0603]
C10  4.7uF  [0603]
C11  1uF  [0402]
D1  RED  [0603]
J2  CAMERA1P_INPUT  [32k141-40m-fr4wvia]
J3  CAMERA1_BNC_INPUT  [BNC-Jack_smrt_112740-13]
J4  CAMERA1N_INPUT  [32k141-40m-fr4wvia]
L1  6.8nH  [0402]
Q1  FDV301N  [SOT23]
R1  250  [0402]
R2  DNI_0  [0402]
R3  DNI_0  [0402]
R4  4.99K  [0402]
R5  4.99K  [0402]
R6  DNI_4.99K  [0402]
R7  4.99K  [0402]
R8  DNI_0  [0402]
R9  0  [0402]
R10  75  [0402]
R11  75  [0402]
R12  0  [0402]
R13  DNI_0  [0402]
R14  37.4  [0402]
U1  LMH0034  [SOIC16]  (sections A,B,C)
sheet S04 CAMERA INPUT 2
C12  0.1uF  [0402]
C13  0.1uF  [0402]
C14  0.01uF  [0402]
C15  0.01uF  [0402]
C16  1uF  [0402]
C17  100pF  [0402]
C18  100pF  [0402]
C19  1uF  [0603]
C20  4.7uF  [0603]
C21  4.7uF  [0603]
C22  1uF  [0402]
D2  RED  [0603]
J5  CAMERA2P_INPUT  [32k141-40m-fr4wvia]
J6  CAMERA2_BNC_INPUT  [BNC-Jack_smrt_112740-13]
J7  CAMERA1N_INPUT  [32k141-40m-fr4wvia]
L2  6.8nH  [0402]
Q2  FDV301N  [SOT23]
R15  250  [0402]
R16  DNI_0  [0402]
R17  DNI_0  [0402]
R18  4.99K  [0402]
R19  4.99K  [0402]
R20  DNI_4.99K  [0402]
R21  4.99K  [0402]
R22  DNI_0  [0402]
R23  0  [0402]
R24  75  [0402]
R25  75  [0402]
R26  0  [0402]
R27  DNI_0  [0402]
R28  37.4  [0402]
U2  LMH0034  [SOIC16]  (sections A,B,C)
sheet S05 CAMERA INPUT 3
C23  0.1uF  [0402]
C24  0.1uF  [0402]
C25  0.01uF  [0402]
C26  0.01uF  [0402]
C27  100pF  [0402]
C28  1uF  [0402]
C29  100pF  [0402]
C30  1uF  [0603]
C31  4.7uF  [0603]
C32  4.7uF  [0603]
C33  1uF  [0402]
D3  RED  [0603]
J8  CAMERA3P_INPUT  [32k141-40m-fr4wvia]
J9  CAMERA3_BNC_INPUT  [BNC-Jack_smrt_112740-13]
J10  CAMERA3N_INPUT  [32k141-40m-fr4wvia]
L3  6.8nH  [0402]
Q3  FDV301N  [SOT23]
R29  250  [0402]
R30  DNI_0  [0402]
R31  DNI_0  [0402]
R32  4.99K  [0402]
R33  4.99K  [0402]
R34  DNI_4.99K  [0402]
R35  4.99K  [0402]
R36  DNI_0  [0402]
R37  0  [0402]
R38  75  [0402]
R39  75  [0402]
R40  0  [0402]
R41  DNI_0  [0402]
R42  37.4  [0402]
U3  LMH0034  [SOIC16]  (sections A,B,C)
sheet S06 CAMERA INPUT 4
C34  0.1uF  [0402]
C35  0.1uF  [0402]
C36  0.01uF  [0402]
C37  0.01uF  [0402]
C38  100pF  [0402]
C39  1uF  [0402]
C40  100pF  [0402]
C41  1uF  [0603]
C42  4.7uF  [0603]
C43  4.7uF  [0603]
C44  1uF  [0402]
D4  RED  [0603]
J11  CAMERA4P_INPUT  [32k141-40m-fr4wvia]
J12  CAMERA4_BNC_INPUT  [BNC-Jack_smrt_112740-13]
J13  CAMERA4N_INPUT  [32k141-40m-fr4wvia]
L4  6.8nH  [0402]
Q4  FDV301N  [SOT23]
R43  250  [0402]
R44  DNI_0  [0402]
R45  DNI_0  [0402]
R46  4.99K  [0402]
R47  4.99K  [0402]
R48  DNI_4.99K  [0402]
R49  4.99K  [0402]
R50  DNI_0  [0402]
R51  0  [0402]
R52  75  [0402]
R53  75  [0402]
R54  0  [0402]
R55  DNI_0  [0402]
R56  37.4  [0402]
U4  LMH0034  [SOIC16]  (sections A,B,C)
sheet S07 OUTPUT SIGNALS 1
C45  1uF  [0402]
C46  4.7uF  [0603]
C47  0.1uF  [0402]
C48  4.7uF  [0603]
C49  1uF  [0402]
C50  1uF  [0402]
C51  4.7uF  [0603]
C52  4.7uF  [0603]
C53  0.1uF  [0402]
C54  1uF  [0402]
C55  0.1uF  [0402]
C56  0.1uF  [0402]
J14  MONITOR2_SDI_OUTPUT  [BNC-Jack_smrt_112740-13]
J15  MONITOR1_SDI_OUTPUT  [BNC-Jack_smrt_112740-13]
L5  5.6nH  [0402]
L6  5.6nH  [0402]
L7  5.6nH  [0402]
L8  5.6nH  [0402]
R57  75  [0402]
R58  75  [0402]
R59  75  [0402]
R60  75  [0402]
R61  49.9  [0402]
R62  75  [0402]
R63  49.9  [0402]
R64  75  [0402]
R65  75  [0402]
R66  49.9  [0402]
R67  75  [0402]
R68  75  [0402]
R69  49.9  [0402]
R70  75  [0402]
R71  750  [0402]
R72  750  [0402]
R73  DNI_0  [0402]
R74  DNI_0  [0402]
R75  4.99K  [0402]
R76  4.99K  [0402]
U5  LMH0202  [TSSOP16]  (sections A,B,C)
sheet S08 OUTPUT SIGNALS 2
C57  1uF  [0402]
C58  4.7uF  [0603]
C59  0.1uF  [0402]
C60  4.7uF  [0603]
C61  1uF  [0402]
C62  1uF  [0402]
C63  4.7uF  [0603]
C64  4.7uF  [0603]
C65  0.1uF  [0402]
C66  1uF  [0402]
C67  0.1uF  [0402]
C68  0.1uF  [0402]
J16  MONITOR4_SDI_OUTPUT  [BNC-Jack_smrt_112740-13]
J17  MONITOR3_SDI_OUTPUT  [BNC-Jack_smrt_112740-13]
L9  5.6nH  [0402]
L10  5.6nH  [0402]
L11  5.6nH  [0402]
L12  5.6nH  [0402]
R77  75  [0402]
R78  75  [0402]
R79  75  [0402]
R80  49.9  [0402]
R81  75  [0402]
R82  75  [0402]
R83  49.9  [0402]
R84  75  [0402]
R85  75  [0402]
R86  49.9  [0402]
R87  75  [0402]
R88  49.9  [0402]
R89  75  [0402]
R90  75  [0402]
R91  750  [0402]
R92  750  [0402]
R93  DNI_0  [0402]
R94  DNI_0  [0402]
R95  4.99K  [0402]
R96  4.99K  [0402]
U6  LMH0202  [TSSOP16]  (sections A,B,C)
sheet S09COMMON SIGNALS
J1  SEAM_ASP-134488-01  [ASP-134488]  (sections A,B,C,D,E,F,G,H,I,J,K)
sheet S10 POWER
C69  68uF  [1210]
C70  10uF  [0805]
C71  1uF  [1206]
C72  0.1uF  [1206]
C73  0.01uF  [0805]
C74  68uF  [1210]
C75  10uF  [0805]
C76  1uF  [1206]
C77  0.1uF  [1206]
C78  0.01uF  [0805]
C79  100uF  [1812]
C80  4.7uF  [0603]
C81  1uF  [0603]
C82  68uF  [1210]
C83  10uF  [1210]
C84  1uF  [1210]
C85  68uF  [1210]
C86  10uF  [0805]
C87  1uF  [1206]
C88  0.1uF  [1206]
C89  0.01uF  [0805]
C90  10pF  [0603]
C91  68uF  [1210]
C92  10uF  [0805]
C93  1uF  [1206]
C94  0.1uF  [1206]
C95  0.01uF  [0805]
D5  BAT60A 10V, 3A  [SOD323]
D6  GREEN  [0603]
D7  GREEN  [0603]
D8  BLUE  [0603]
D9  GREEN  [0603]
D10  GREEN  [0603]
JMP1  3 Pin Berg  [HDR_THVT_1X3_100]
JMP2  2 Pin Berg Jumper  [berg2]
JMP3  2 Pin Berg Jumper  [berg2]
JMP4  2 Pin Berg Jumper  [berg2]
L13  Ferrite Bead_1210  [1210]
L14  Ferrite Bead_1210  [1210]
L15  Ferrite Bead_1210  [1210]
L16  Ferrite Bead_1210  [1210]
P1  GND  [JACK_THVT_BANANA_500DIA]
P2  5V_BJ  [JACK_THVT_BANANA_500DIA]
P3  RAPC722  [con_rapc722_jack_thvt_3]
R97  250  [0402]
R98  250  [0402]
R99  4.99K  [0603]
R100  3.57K  [0603]
R101  1.13K  [0603]
R102  3  [0603]
R103  1.2K  [0402]
R104  250  [0402]
R105  250  [0402]
U7  TPS74401RGW  [RGW20]

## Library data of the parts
C1-C68 C79-C81 C90 = CAP_NP
D1 = LED_HSMS: TI_SILKTEXT: CAMERA 1
J2 = sma_surface_0: TI_SILKTEXT: CAM1P_IN
J3 = SMA_SMP_FR4: Part_Number: 112740-13; TI_SILKTEXT: CAM 1
J4 = sma_surface_0: TI_SILKTEXT: CAM1N_IN
L1-L12 = Inductor_1210
Q1-Q4 = FDV301N_NFET_1
R1-R98 R103-R105 = r0402
U1-U4 = LMH0034
D2 = LED_HSMS: TI_SILKTEXT: CAMERA 2
J5 = sma_surface_0: TI_SILKTEXT: CAM2P_IN
J6 = SMA_SMP_FR4: Part_Number: 112740-13; TI_SILKTEXT: CAM 2
J7 = sma_surface_0: TI_SILKTEXT: CAM2N_IN
D3 = LED_HSMS: TI_SILKTEXT: CAMERA 3
J8 = sma_surface_0: TI_SILKTEXT: CAN3P_IN
J9 = SMA_SMP_FR4: Part_Number: 112740-13; TI_SILKTEXT: CAM 3
J10 = sma_surface_0: TI_SILKTEXT: CAM3N_IN
D4 = LED_HSMS: TI_SILKTEXT: CAMERA 4
J11 = sma_surface_0: TI_SILKTEXT: CAM4P_IN
J12 = SMA_SMP_FR4: Part_Number: 112740-13; TI_SILKTEXT: CAM 4
J13 = sma_surface_0: TI_SILKTEXT: CAM4N_IN
J14 = SMA_SMP_FR4: Part_Number: 112740-13; TI_SILKTEXT: MON2_SDI_OUT
J15 = SMA_SMP_FR4: Part_Number: 112740-13; TI_SILKTEXT: MON1_SDI_OUT
U5 U6 = LMH0202
J16 = SMA_SMP_FR4: Part_Number: 112740-13; TI_SILKTEXT: MON4_SDI_OUT
J17 = SMA_SMP_FR4: Part_Number: 112740-13; TI_SILKTEXT: MON3_SDI_OUT
J1 = SEAM_ASP-134488-01
C69 C71 C74 C76 C82-C85 C87 C91 C93 = NPCap1206_1.0uf
C70 C75 C86 C92 = CAP_NP: Vendor: Digi-Key
C72 C77 C88 C94 = NPCap1206_0.1uf
C73 C78 C89 C95 = NPCap0805_0.01uf
D5 = BAT60A
D6 = LED_HSMG: TI_SILKTEXT: 3P3V_LVDS101
D7 = LED_HSMG: TI_SILKTEXT: 3P3V_LMH0202
D8 = LED_HSMB: TI_SILKTEXT: 5V
D9 = LED_HSMG: TI_SILKTEXT: 3P3V
D10 = LED_HSMG: TI_SILKTEXT: 3P3V_LMH0034
JMP1 = 3_Pin_Berg_Jumper: TI_SILKTEXT: 5V_SOURCE
JMP2 = 2_Pin_Berg_Jumper: TI_SILKTEXT: 3P3V_LVDS101
JMP3 = 2_Pin_Berg_Jumper: TI_SILKTEXT: 3P3V_LMH0202
JMP4 = 2_Pin_Berg_Jumper: TI_SILKTEXT: 3P3V_LMH0034
L13-L16 = Ferrite_Bead_1206
P1 P2 = Banana-Jack
P3 = RAPC722: SILK: +5V
R99-R102 = r0603
U7 = TPS74x01RGW_0

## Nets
5V: C69.1 C70.1 C71.1 C72.1 C73.1 C79.1 C80.1 C81.1 L13.2 R99.1 R103.1 U7.5(IN1) U7.6(IN2) U7.7(IN3) U7.8(IN4) U7.10(BIAS)
5V_BARREL: D5.2(A) P3.3(TIP)
5V_BJ: JMP1.1 P2.1(V)
5V_DIODE: D5.1(C) JMP1.3
5V_SOURCE: JMP1.2 L13.1
GND: C1.2 C2.2 C3.2 C4.2 C6.2 C7.2 C12.2 C13.2 C14.2 C15.2 C17.2 C18.2 C23.2 C24.2 C25.2 C26.2 C27.2 C29.2 C34.2 C35.2 C36.2 C37.2 C38.2 C40.2 C47.2 C53.2 C55.2 C56.2 C59.2 C65.2 C67.2 C68.2 C69.2 C70.2 C71.2 C72.2 C73.2 C74.2 C75.2 C76.2 C77.2 C78.2 C79.2 C80.2 C81.2 C82.2 C83.2 C84.2 C85.2 C86.2 C87.2 C88.2 C89.2 C90.2 C91.2 C92.2 C93.2 C94.2 C95.2 D6.1 D7.1 D8.1 D9.1 D10.1 J1.A1 J1.A4 J1.A5 J1.A8 J1.A9 J1.A12 J1.A13 J1.A16 J1.A17 J1.A20 J1.A21 J1.A24 J1.A25 J1.A28 J1.A29 J1.A32 J1.A33 J1.A36 J1.A38 J1.A40 J1.B1 J1.B2 J1.B3 J1.B4 J1.B5 J1.B6 J1.B7 J1.B8 J1.B9 J1.B10 J1.B11 J1.B12 J1.B13 J1.B14 J1.B15 J1.B16 J1.B17 J1.B18 J1.B19 J1.B20 J1.B21 J1.B22 J1.B23 J1.B24 J1.B25 J1.B26 J1.B27 J1.B28 J1.B29 J1.B30 J1.B31 J1.B32 J1.B33 J1.B34 J1.B35 J1.B36 J1.B37 J1.B38 J1.B39 J1.B40 J1.E2 J1.E4 J1.F1 J1.F2 J1.F3 J1.F4 J1.J1 J1.J2 J1.J3 J1.J4 J1.J5 J1.J6 J1.J7 J1.J8 J1.J9 J1.J10 J1.J11 J1.J12 J1.J13 J1.J14 J1.J15 J1.J16 J1.J17 J1.J18 J1.J19 J1.J20 J1.J21 J1.J22 J1.J23 J1.J24 J1.J25 J1.J26 J1.J27 J1.J28 J1.J29 J1.J30 J1.J31 J1.J32 J1.J33 J1.J34 J1.J35 J1.J36 J1.J37 J1.J38 J1.J39 J1.J40 J1.K1 J1.K4 J1.K5 J1.K8 J1.K9 J1.K12 J1.K13 J1.K16 J1.K17 J1.K20 J1.K21 J1.K24 J1.K25 J1.K28 J1.K29 J1.K32 J1.K33 J1.K36 J1.K38 J1.K40 J2.2 J2.3 J2.4 J2.5 J3.2 J3.3 J3.4 J3.5 J4.2 J4.3 J4.4 J4.5 J5.2 J5.3 J5.4 J5.5 J6.2 J6.3 J6.4 J6.5 J7.2 J7.3 J7.4 J7.5 J8.2 J8.3 J8.4 J8.5 J9.2 J9.3 J9.4 J9.5 J10.2 J10.3 J10.4 J10.5 J11.2 J11.3 J11.4 J11.5 J12.2 J12.3 J12.4 J12.5 J13.2 J13.3 J13.4 J13.5 J14.2 J14.3 J14.4 J14.5 J15.2 J15.3 J15.4 J15.5 J16.2 J16.3 J16.4 J16.5 J17.2 J17.3 J17.4 J17.5 P1.1(V) P3.1(SLEEVE) Q1.2(S) Q2.2(S) Q3.2(S) Q4.2(S) R3.2 R5.2 R7.2 R11.2 R14.1 R17.2 R19.2 R21.2 R25.2 R28.1 R31.2 R33.2 R35.2 R39.2 R42.1 R45.2 R47.2 R49.2 R53.2 R56.1 R65.1 R70.1 R75.1 R76.1 R85.1 R90.1 R95.1 R96.1 R102.1 U1.3(VEE1) U1.6(VEE2) U1.11(VEE3) U1.14(VEE4) U2.3(VEE1) U2.6(VEE2) U2.11(VEE3) U2.14(VEE4) U3.3(VEE1) U3.6(VEE2) U3.11(VEE3) U3.14(VEE4) U4.3(VEE1) U4.6(VEE2) U4.11(VEE3) U4.14(VEE4) U5.3(VEE1) U5.7(VEE2) U6.3(VEE1) U6.7(VEE2) U7.12(GND) U7.21(GND_PP)
GND_DECOUPLE1: C53.1 R66.1 R69.2
GND_DECOUPLE2: C47.1 R61.2 R63.1
GND_DECOUPLE3: C65.1 R86.1 R88.2
GND_DECOUPLE4: C59.1 R80.2 R83.1
3P3V: C82.1 C83.1 C84.1 JMP2.2 JMP3.2 JMP4.2 R100.1 R104.1 U7.1(OUT1) U7.18(OUT2) U7.19(OUT3) U7.20(OUT4)
3P3V_0034: JMP4.1 L16.1
3P3V_101: JMP2.1 L14.1
3P3V_0202: JMP3.1 L15.1
3P3V_LMH0034: C1.1 C2.1 C12.1 C13.1 C23.1 C24.1 C34.1 C35.1 C91.1 C92.1 C93.1 C94.1 C95.1 L16.2 R1.1 R2.1 R4.1 R6.1 R15.1 R16.1 R18.1 R20.1 R29.1 R30.1 R32.1 R34.1 R43.1 R44.1 R46.1 R48.1 R105.1 U1.2(VCC1) U1.15(VCC2) U2.2(VCC1) U2.15(VCC2) U3.2(VCC1) U3.15(VCC2) U4.2(VCC1) U4.15(VCC2)
3P3V_LMH0202: C55.1 C56.1 C67.1 C68.1 C85.1 C86.1 C87.1 C88.1 C89.1 L15.2 R57.2 R58.2 R59.2 R60.2 R71.2 R72.2 R73.2 R74.2 R77.2 R78.2 R79.2 R81.2 R91.2 R92.2 R93.2 R94.2 R98.1 U5.9(VCC2) U5.13(VCC1) U6.9(VCC2) U6.13(VCC1)
3P3V_LVDS101: C74.1 C75.1 C76.1 C77.1 C78.1 L14.2 R97.1
3P3V_REG_TRIM: R101.1 R102.2
3P3VREG_ADJ: R100.2 R101.2 U7.16(FB)
3P3VREG_SS: C90.1 U7.15(SS)
/CD/MUTE1: C3.1 Q1.1(G) R2.2 R3.1 U1.16(/CD/MUTE)
/CD/MUTE2: C14.1 Q2.1(G) R16.2 R17.1 U2.16(/CD/MUTE)
/CD/MUTE3: C25.1 Q3.1(G) R30.2 R31.1 U3.16(/CD/MUTE)
/CD/MUTE4: C36.1 Q4.1(G) R44.2 R45.1 U4.16(/CD/MUTE)
/SDI1_MON1_IN: C54.2 R69.1 U5.6(/SDI2)
/SDI2_MON2_IN: C49.2 R63.2 U5.2(/SDI1)
/SDI3_MON3_IN: C66.2 R88.1 U6.6(/SDI2)
/SDI4_MON4_IN: C61.2 R83.2 U6.2(/SDI1)
/SDO1_OUT: L8.1 R60.1 R68.1 U5.11(/SDO2)
/SDO2_OUT: L6.1 R58.1 R64.1 U5.15(/SDO1)
/SDO3_OUT: L12.1 R81.1 R89.1 U6.11(/SDO2)
/SDO4_OUT: L10.1 R78.1 R84.1 U6.15(/SDO1)
/SDO_MON1_OUT: C52.1 L8.2 R68.2
/SDO_MON1_TERM: C52.2 R70.2
/SDO_MON2_OUT: C48.1 L6.2 R64.2
/SDO_MON2_TERM: C48.2 R65.2
/SDO_MON3_OUT: C64.1 L12.2 R89.2
/SDO_MON3_TERM: C64.2 R90.2
/SDO_MON4_OUT: C60.1 L10.2 R84.2
/SDO_MON4_TERM: C60.2 R85.2
AEC+1: C5.1 U1.7(AEC+)
AEC+2: C16.1 U2.7(AEC+)
AEC+3: C28.1 U3.7(AEC+)
AEC+4: C39.1 U4.7(AEC+)
AEC-1: C5.2 U1.8(AEC-)
AEC-2: C16.2 U2.8(AEC-)
AEC-3: C28.2 U3.8(AEC-)
AEC-4: C39.2 U4.8(AEC-)
BYPASS1: C7.1 R6.2 R7.1 U1.9(BYPASS)
BYPASS2: C18.1 R20.2 R21.1 U2.9(BYPASS)
BYPASS3: C29.1 R34.2 R35.1 U3.9(BYPASS)
BYPASS4: C40.1 R48.2 R49.1 U4.9(BYPASS)
CAMERA1_BNC_INPUT: J3.1 L1.1 R10.1
CAMERA1N_INPUT: J1.K30 R12.2
CAMERA1N_SMA_OUT: J4.1 R13.2
CAMERA1P_INPUT: J1.K31 R9.2
CAMERA1P_SMA_OUT: J2.1 R8.1
CAMERA2_BNC_INPUT: J6.1 L2.1 R24.1
CAMERA2N_INPUT: J1.K22 R26.2
CAMERA2N_SMA_OUT: J7.1 R27.2
CAMERA2P_INPUT: J1.K23 R23.2
CAMERA2P_SMA_OUT: J5.1 R22.1
CAMERA3_BNC_INPUT: J9.1 L3.1 R38.1
CAMERA3N_INPUT: J1.K10 R40.2
CAMERA3N_SMA_OUT: J10.1 R41.2
CAMERA3P_INPUT: J1.K11 R37.2
CAMERA3P_SMA_OUT: J8.1 R36.1
CAMERA4_BNC_INPUT: J12.1 L4.1 R52.1
CAMERA4N_INPUT: J1.K2 R54.2
CAMERA4N_SMA_OUT: J13.1 R55.2
CAMERA4P_INPUT: J1.K3 R51.2
CAMERA4P_SMA_OUT: J11.1 R50.1
CLI1: C4.1 U1.1(CLI)
CLI2: C15.1 U2.1(CLI)
CLI3: C26.1 U3.1(CLI)
CLI4: C37.1 U4.1(CLI)
EN: R99.2 U7.11(EN)
LED1A: D1.2 R1.2
LED1C: D1.1 Q1.3(D)
LED2A: D2.2 R15.2
LED2C: D2.1 Q2.3(D)
LED3A: D3.2 R29.2
LED3C: D3.1 Q3.3(D)
LED3P3VA: D9.2 R104.2
LED4A: D4.2 R43.2
LED4C: D4.1 Q4.3(D)
LED5V: D8.2 R103.2
LED_LMH0034: D10.2 R105.2
LED_LMH0202: D7.2 R98.2
LED_LVDSA: D6.2 R97.2
LMH0034_/SDI1: C11.1 U1.5(/SDI)
LMH0034_/SDI2: C22.1 U2.5(/SDI)
LMH0034_/SDI3: C33.1 U3.5(/SDI)
LMH0034_/SDI4: C44.1 U4.5(/SDI)
LMH0034_/SDO1: C10.1 U1.12(/SDO)
LMH0034_/SDO2: C21.1 U2.12(/SDO)
LMH0034_/SDO3: C32.1 U3.12(/SDO)
LMH0034_/SDO4: C43.1 U4.12(/SDO)
LMH0034_AC_IN1: C8.2 U1.4(SDI)
LMH0034_AC_IN2: C19.2 U2.4(SDI)
LMH0034_AC_IN3: C30.2 U3.4(SDI)
LMH0034_AC_IN4: C41.2 U4.4(SDI)
LMH0034_IN1: C8.1 L1.2 R10.2 R11.1
LMH0034_IN2: C19.1 L2.2 R24.2 R25.1
LMH0034_IN3: C30.1 L3.2 R38.2 R39.1
LMH0034_IN4: C41.1 L4.2 R52.2 R53.1
LMH0034_SDO1: C9.1 U1.13(SDO)
LMH0034_SDO2: C20.1 U2.13(SDO)
LMH0034_SDO3: C31.1 U3.13(SDO)
LMH0034_SDO4: C42.1 U4.13(SDO)
LMH0034_TERM1: C11.2 R14.2
LMH0034_TERM2: C22.2 R28.2
LMH0034_TERM3: C33.2 R42.2
LMH0034_TERM4: C44.2 R56.2
MONITOR1_SDI_OUTPUT: C51.2 J15.1
MONITOR1N_OUTPUT: C54.1 J1.K27
MONITOR1P_OUTPUT: C50.1 J1.K26
MONITOR2_SDI_OUTPUT: C46.2 J14.1
MONITOR2N_OUTPUT: C49.1 J1.K19
MONITOR2P_OUTPUT: C45.1 J1.K18
MONITOR3_SDI_OUTPUT: C63.2 J17.1
MONITOR3N_OUTPUT: C66.1 J1.K15
MONITOR3P_OUTPUT: C62.1 J1.K14
MONITOR4_SDI_OUTPUT: C58.2 J16.1
MONITOR4N_OUTPUT: C61.1 J1.K7
MONITOR4P_OUTPUT: C57.1 J1.K6
MUTEREF1: C6.1 R4.2 R5.1 U1.10(MUTEREF)
MUTEREF2: C17.1 R18.2 R19.1 U2.10(MUTEREF)
MUTEREF3: C27.1 R32.2 R33.1 U3.10(MUTEREF)
MUTEREF4: C38.1 R46.2 R47.1 U4.10(MUTEREF)
RREF1_1: R72.1 U5.4(RREF1)
RREF1_2: R92.1 U6.4(RREF1)
RREF2_1: R71.1 U5.8(RREF2)
RREF2_2: R91.1 U6.8(RREF2)
SD/HD1_1: R74.1 R76.2 U5.14(SD/HD1)
SD/HD1_2: R94.1 R96.2 U6.14(SD/HD1)
SD/HD2_1: R73.1 R75.2 U5.10(SD/HD2)
SD/HD2_2: R93.1 R95.2 U6.10(SD/HD2)
SDI1_MON1_IN: C50.2 R66.2 U5.5(SDI2)
SDI2_MON2_IN: C45.2 R61.1 U5.1(SDI1)
SDI3_MON3_IN: C62.2 R86.2 U6.5(SDI2)
SDI4_MON4_IN: C57.2 R80.1 U6.1(SDI1)
SDO1_OUT: L7.1 R59.1 R67.1 U5.12(SDO2)
SDO2_OUT: L5.1 R57.1 R62.1 U5.16(SDO1)
SDO3_OUT: L11.1 R79.1 R87.1 U6.12(SDO2)
SDO4_OUT: L9.1 R77.1 R82.1 U6.16(SDO1)
SDO_MON1_OUT: C51.1 L7.2 R67.2
SDO_MON2_OUT: C46.1 L5.2 R62.2
SDO_MON3_OUT: C63.1 L11.2 R87.2
SDO_MON4_OUT: C58.1 L9.2 R82.2
TO_TLK1N1: C10.2 R12.1 R13.1
TO_TLK1P1: C9.2 R8.2 R9.1
TO_TLK2N1: C21.2 R26.1 R27.1
TO_TLK2P1: C20.2 R22.2 R23.1
TO_TLK3N1: C32.2 R40.1 R41.1
TO_TLK3P1: C31.2 R36.2 R37.1
TO_TLK4N1: C43.2 R54.1 R55.1
TO_TLK4P1: C42.2 R50.2 R51.1

Not connected (* = marked no-connect by the designer): J1 A2* A3* A6* A7* A10* A11* A14* A15* A18* A19* A22* A23* A26* A27* A30* A31* A34* A35* A37* A39* C1* C2* C3* C4* C5* C6* C7* C8* C9* C10* C11* C12* C13* C14* C15* C16* C17* C18* C19* C20* C21* C22* C23* C24* C25* C26* C27* C28* C29* C30* C31* C32* C33* C34* C35* C36* C37* C38* C39* C40* D1* D2* D3* D4* D5* D6* D7* D8* D9* D10* D11* D12* D13* D14* D15* D16* D17* D18* D19* D20* D21* D22* D23* D24* D25* D26* D27* D28* D29* D30* D31* D32* D33* D34* D35* D36* D37* D38* D39* D40* E1* E3* E5* E6* E7* E8* E9* E10* E11* E12* E13* E14* E15* E16* E17* E18* E19* E20* E21* E22* E23* E24* E25* E26* E27* E28* E29* E30* E31* E32* E33* E34* E35* E36* E37* E38* E39* E40* F5* F6* F7* F8* F9* F10* F11* F12* F13* F14* F15* F16* F17* F18* F19* F20* F21* F22* F23* F24* F25* F26* F27* F28* F29* F30* F31* F32* F33* F34* F35* F36* F37* F38* F39* F40* G1* G2* G3* G4* G5* G6* G7* G8* G9* G10* G11* G12* G13* G14* G15* G16* G17* G18* G19* G20* G21* G22* G23* G24* G25* G26* G27* G28* G29* G30* G31* G32* G33* G34* G35* G36* G37* G38* G39* G40* H1* H2* H3* H4* H5* H6* H7* H8* H9* H10* H11* H12* H13* H14* H15* H16* H17* H18* H19* H20* H21* H22* H23* H24* H25* H26* H27* H28* H29* H30* H31* H32* H33* H34* H35* H36* H37* H38* H39* H40* I1(MOUNT1)* I2(MOUNT2)* I3(MOUNT3)* I4(MOUNT4)* K34* K35* K37* K39*; P3 2(SHUNT)*; U7 2(NC1)* 3(NC2)* 4(NC3)* 9(PG)* 13(NC4)* 14(NC5)* 17(NC6)*

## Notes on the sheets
sheet 1
- NOTES:
  1.  PLACE NET NAMES ON ALL JUMPERS AND HEADERS.
  2.  PLACE ALL PARTS OTHER THAN SMA CONNECTORS ON A 0 OR 90 DEGREE ORIENTATION.
  3.  SERIAL DATA SHOULD BE ROUTED AS 100 OHM DIFFERENTIALLY COUPLED OR SINGLE-ENDED 75 OHM TRANSMISSION LINES ON
  OUTSIDE LAYERS. ROUTING DISTANCE SHOULD BE 5 INCHES OR LESS.  ALL OTHER DATA LINES SHOULD BE 50 OHM IMPEDIANCE ON
  INTERNAL OR EXTERNAL LAYERS.  ROUTED POWER SHOULD BE A MINIMUM OF 40 MILS WIDE.
  4.  USE FR4-370 MATERIAL FOR ALL LAYERS.
  5.  SERIAL and REFCLK NETS MUST MATCH WITHIN +/- 0.5 MILS
  6.  MATCH DIFFERENTIAL TRACE WIDTHS OF SERIAL DATA LINES.
  7.  PLACE TI LOGO, BOARD NAME, JN COMBO LOGO, AND THE BOARD NUMBER IN TOP SIDE METAL.
- SCHEMATIC SHEET INDEX:
- SHEET 01:  TLK10xxx HD-SDI MOTHER BOARD COVER SHEET AND NOTES
  SHEET 02:  LS INPUTS / OUTPUTS
  SHEET 03:  CAMERA INPUT 1
  SHEET 04:  CAMERA INPUT 2
  SHEET 05:  CAMERA INPUT 3
  SHEET 06:  CAMERA INPUT 4
  SHEET 07:  OUTPUT SIGNALS MONITOR 1 / MONITOR 2
  SHEET 08:  OUTPUT SIGNALS MONITOR 3 / MONITOR 4
  SHEET 09:  COMMON SIGNALS
  SHEET 10:  POWER
- TLK10xxx DATA SHEET REVISION:  x.x.x
  DATA SHEET LAST UPDATED ON:   xx/xx/xx
sheet 2
- CHANNEL B INPUT AND OUTPUT NO CONNECT
sheet 3
- PLACE CAPS
  CLOSE TO VCC PINS
- MATCH P/N
  TRACE LENGTHS
- ROUTE 50 OHMS SINGLE ENDED
- OVERLAP RESISTOR
  PADS R11 AND R17
  IF POSSIBLE
- MATCH P/N
  TRACE LENGTHS
- ROUTE 100 OHMS DIFFERENTIAL
- ROUTE 75 OHMS SINGLE ENDED
- ROUTE 100 OHMS DIFFERENTIAL
- OVERLAP RESISTOR
  PADS R23 AND R19
  IF POSSIBLE
- ROUTE 50 OHMS SINGLE ENDED
- MATCH P/N
  TRACE LENGTHS
sheet 4
- PLACE CAPS
  CLOSE TO VCC PINS
- MATCH P/N
  TRACE LENGTHS
- ROUTE 50 OHMS SINGLE ENDED
- OVERLAP RESISTOR
  PADS R34 AND R40
  IF POSSIBLE
- MATCH P/N
  TRACE LENGTHS
- ROUTE 100 OHMS DIFFERENTIAL
- ROUTE 75 OHMS SINGLE ENDED
- ROUTE 100 OHMS DIFFERENTIAL
- OVERLAP RESISTOR
  PADS R46 AND R42
  IF POSSIBLE
- ROUTE 50 OHMS SINGLE ENDED
- MATCH P/N
  TRACE LENGTHS
sheet 5
- PLACE CAPS
  CLOSE TO VCC PINS
- MATCH P/N
  TRACE LENGTHS
- ROUTE 50 OHMS SINGLE ENDED
- OVERLAP RESISTOR
  PADS R57 AND R63
  IF POSSIBLE
- MATCH P/N
  TRACE LENGTHS
- ROUTE 100 OHMS DIFFERENTIAL
- ROUTE 75 OHMS SINGLE ENDED
- ROUTE 100 OHMS DIFFERENTIAL
- OVERLAP RESISTOR
  PADS R69 AND R65
  IF POSSIBLE
- ROUTE 50 OHMS SINGLE ENDED
- MATCH P/N
  TRACE LENGTHS
sheet 6
- PLACE CAPS
  CLOSE TO VCC PINS
- MATCH P/N
  TRACE LENGTHS
- ROUTE 50 OHMS SINGLE ENDED
- OVERLAP RESISTOR
  PADS R80 AND R86
  IF POSSIBLE
- MATCH P/N
  TRACE LENGTHS
- ROUTE 100 OHMS DIFFERENTIAL
- ROUTE 75 OHMS SINGLE ENDED
- ROUTE 100 OHMS DIFFERENTIAL
- OVERLAP RESISTOR
  PADS R92 AND R88
  IF POSSIBLE
- ROUTE 50 OHMS SINGLE ENDED
- MATCH P/N
  TRACE LENGTHS
sheet 7
- ROUTE 100 OHMS DIFFERENTIAL
- ROUTE 75 OHMS SINGLE ENDED
- ROUTE 75 OHMS SINGLE ENDED
- ROUTE 75 OHMS SINGLE ENDED
- ROUTE 100 OHMS DIFFERENTIAL
- ROUTE 75 OHMS SINGLE ENDED
- PLACE CAPS
  CLOSE TO VCC PINS
sheet 8
- ROUTE 100 OHMS DIFFERENTIAL
- ROUTE 75 OHMS SINGLE ENDED
- ROUTE 75 OHMS SINGLE ENDED
- ROUTE 75 OHMS SINGLE ENDED
- ROUTE 100 OHMS DIFFERENTIAL
- ROUTE 75 OHMS SINGLE ENDED
- PLACE CAPS
  CLOSE TO VCC PINS
sheet 10
- DAUGHTER CARD POWER
- INPUT BUFFER POWER
- NOTE:  PLACE GND BANANA JACKS 750 MIL
  CENTER TO CENTER SPACING WITH A POWER
  BANANA JACK LOCATED BETWEEN TWO POWER
  JACKS.
- INSTALL 0-OHM RESISTOR
- INSTALL 0-OHM RESISTOR
- INSTALL 0-OHM RESISTOR
- INSTALL 0-OHM RESISTOR
